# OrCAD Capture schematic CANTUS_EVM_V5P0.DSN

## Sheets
1 01. CANTUS: size A3; title: CANTUS EVM BOARD
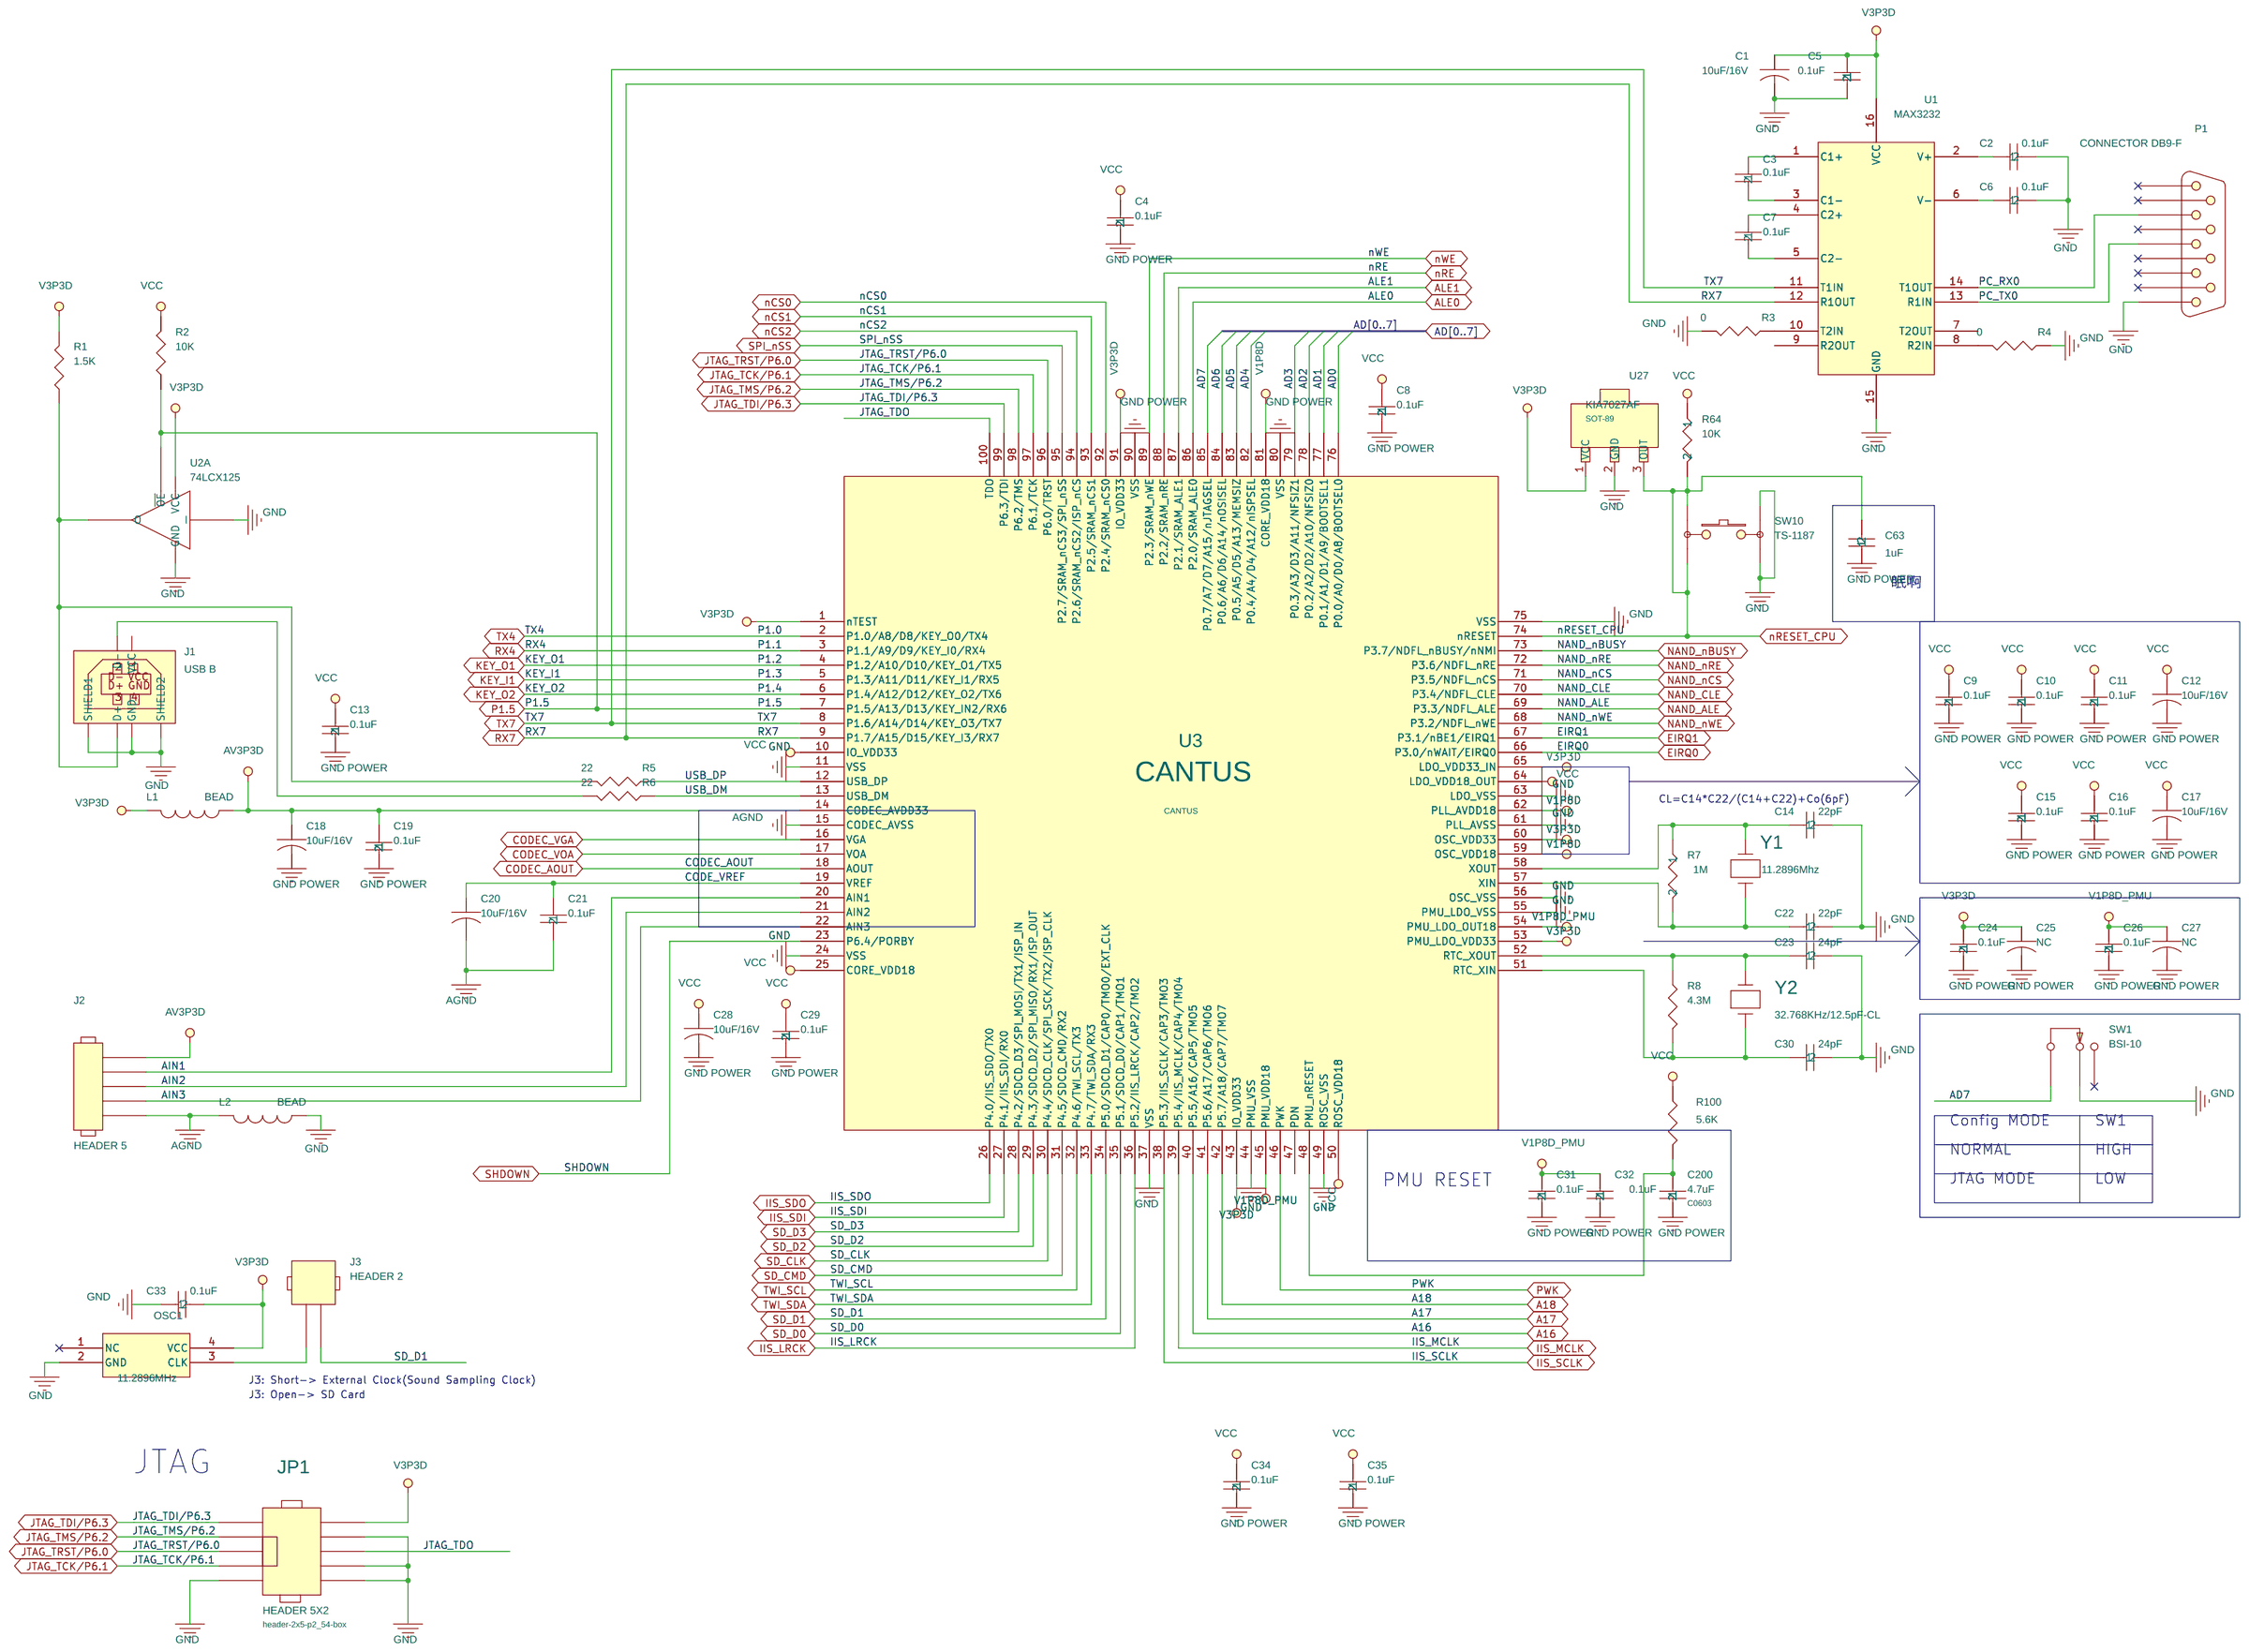
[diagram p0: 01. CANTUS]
2 02. CANTUS Audio DAC & KEY: size A3; rev: 5.0; note: CANTUS DAC & KEY
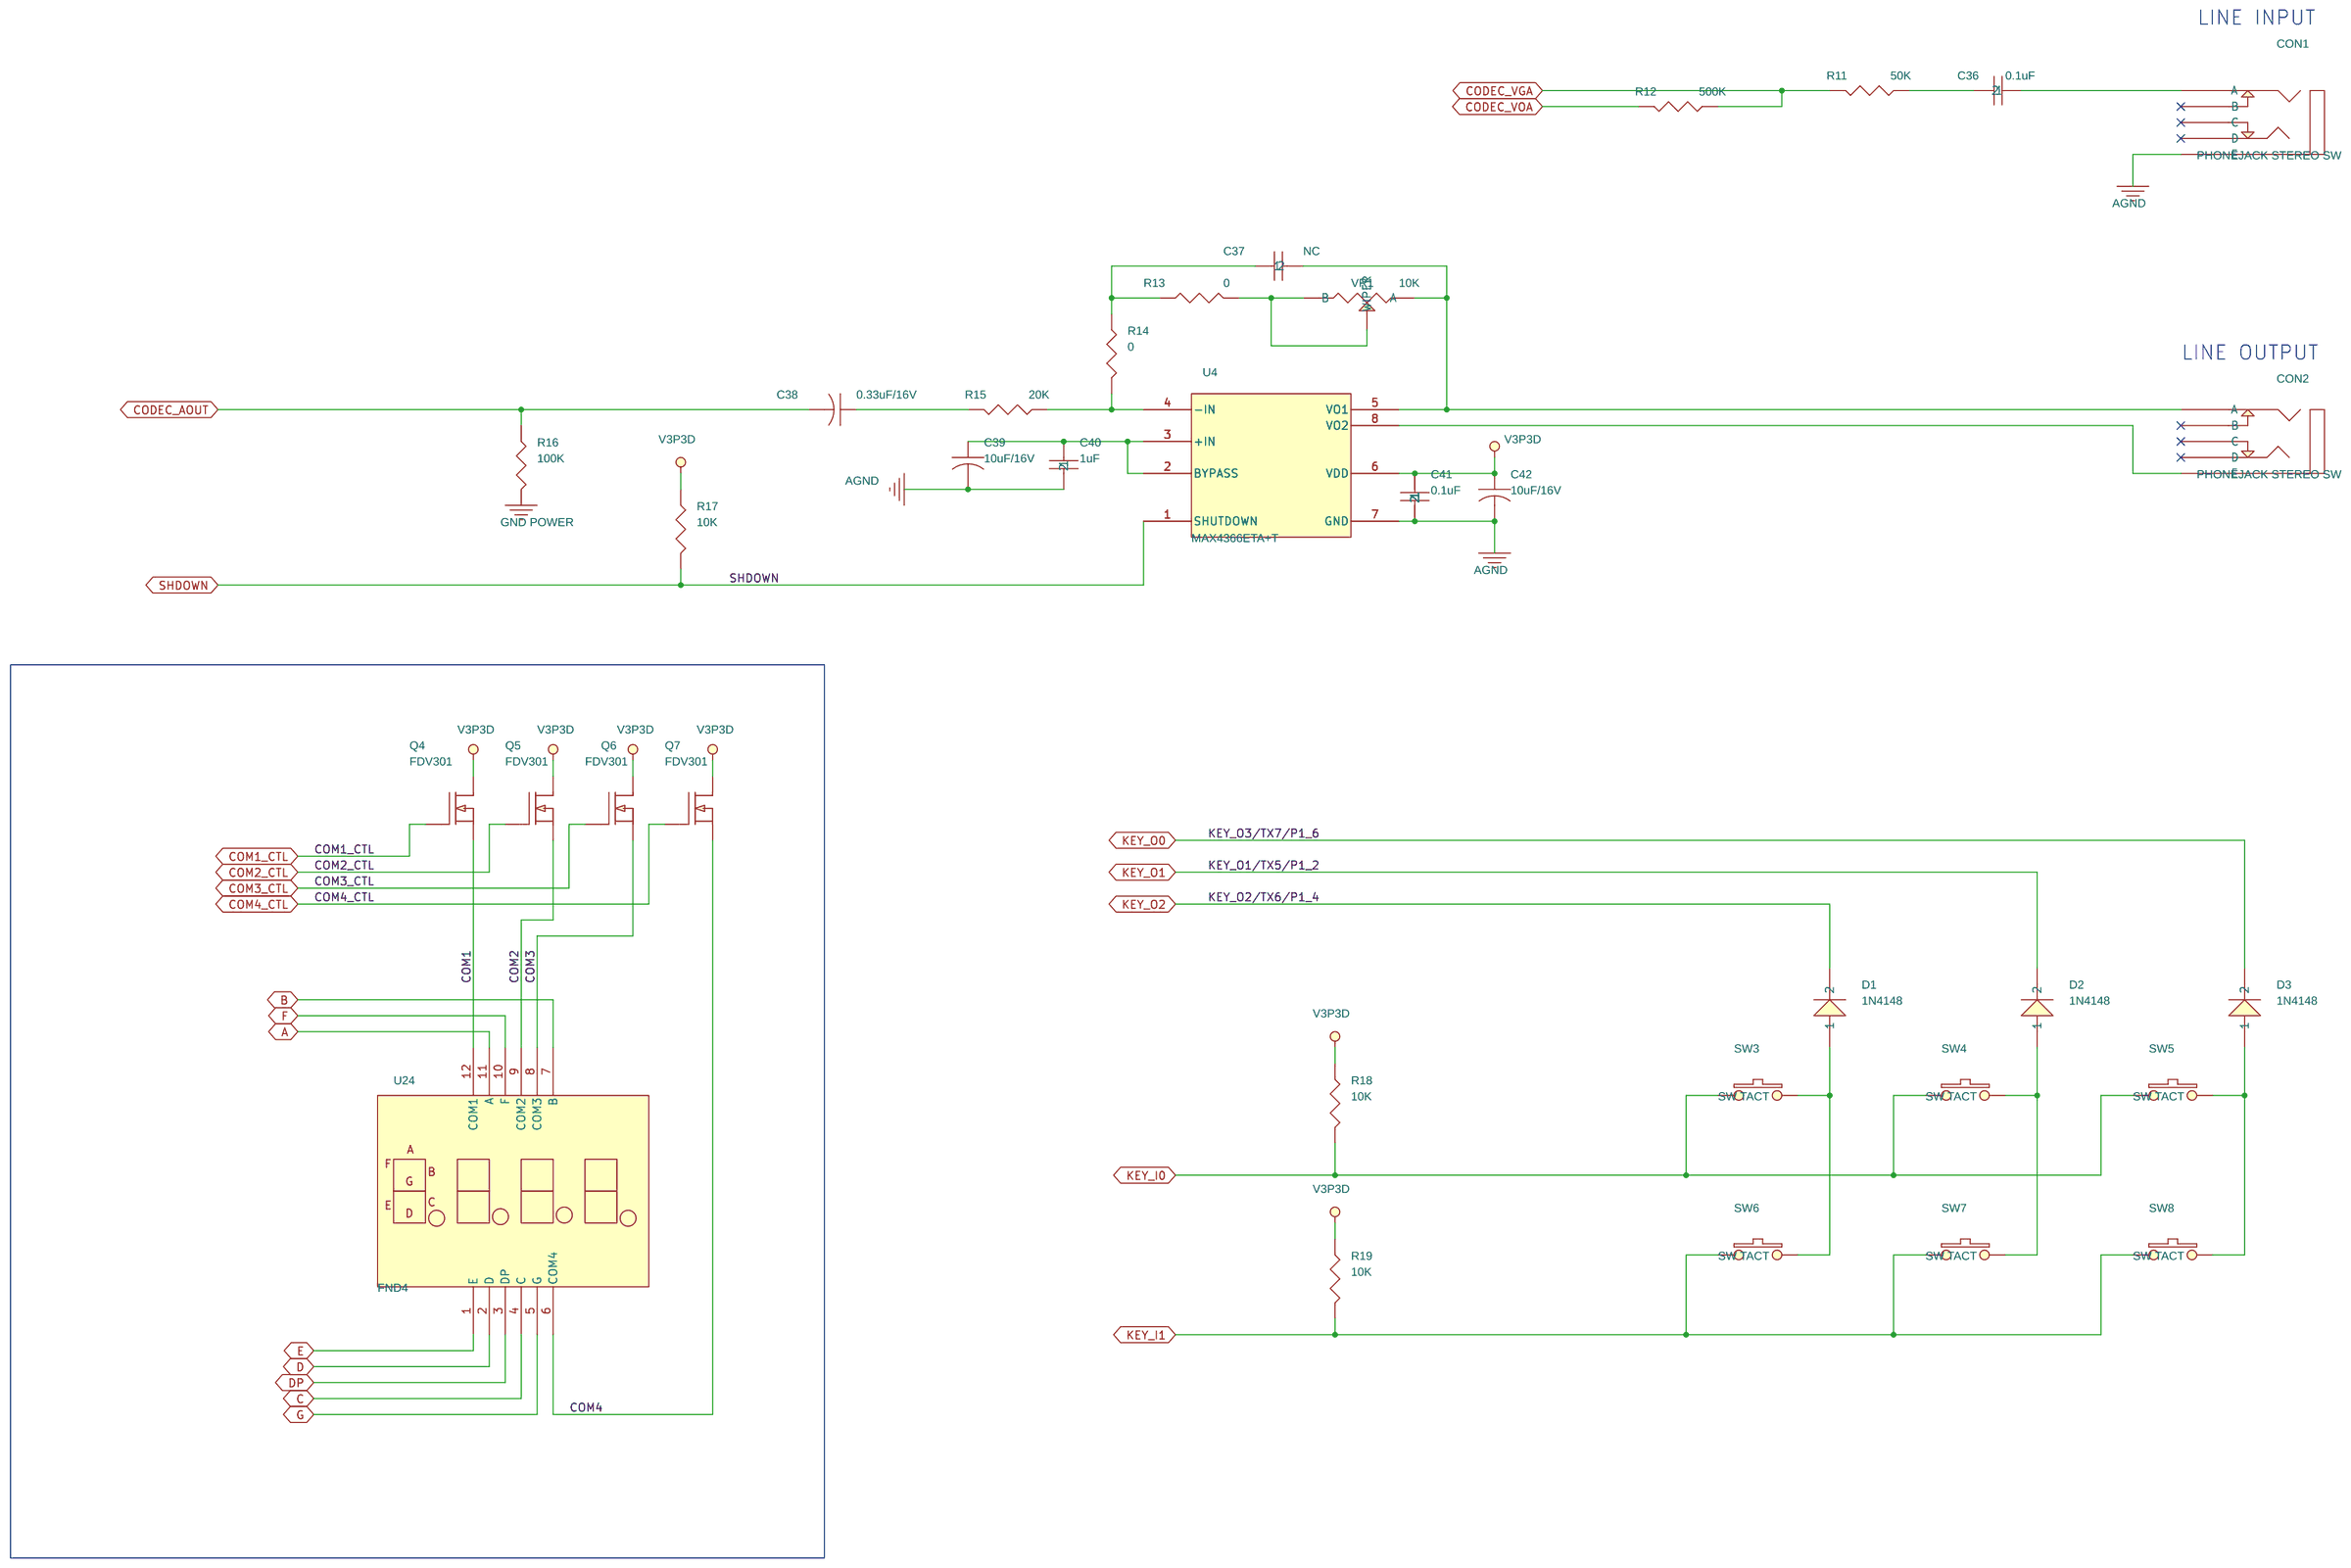
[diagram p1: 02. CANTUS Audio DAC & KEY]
3 03. Buffer: size A3
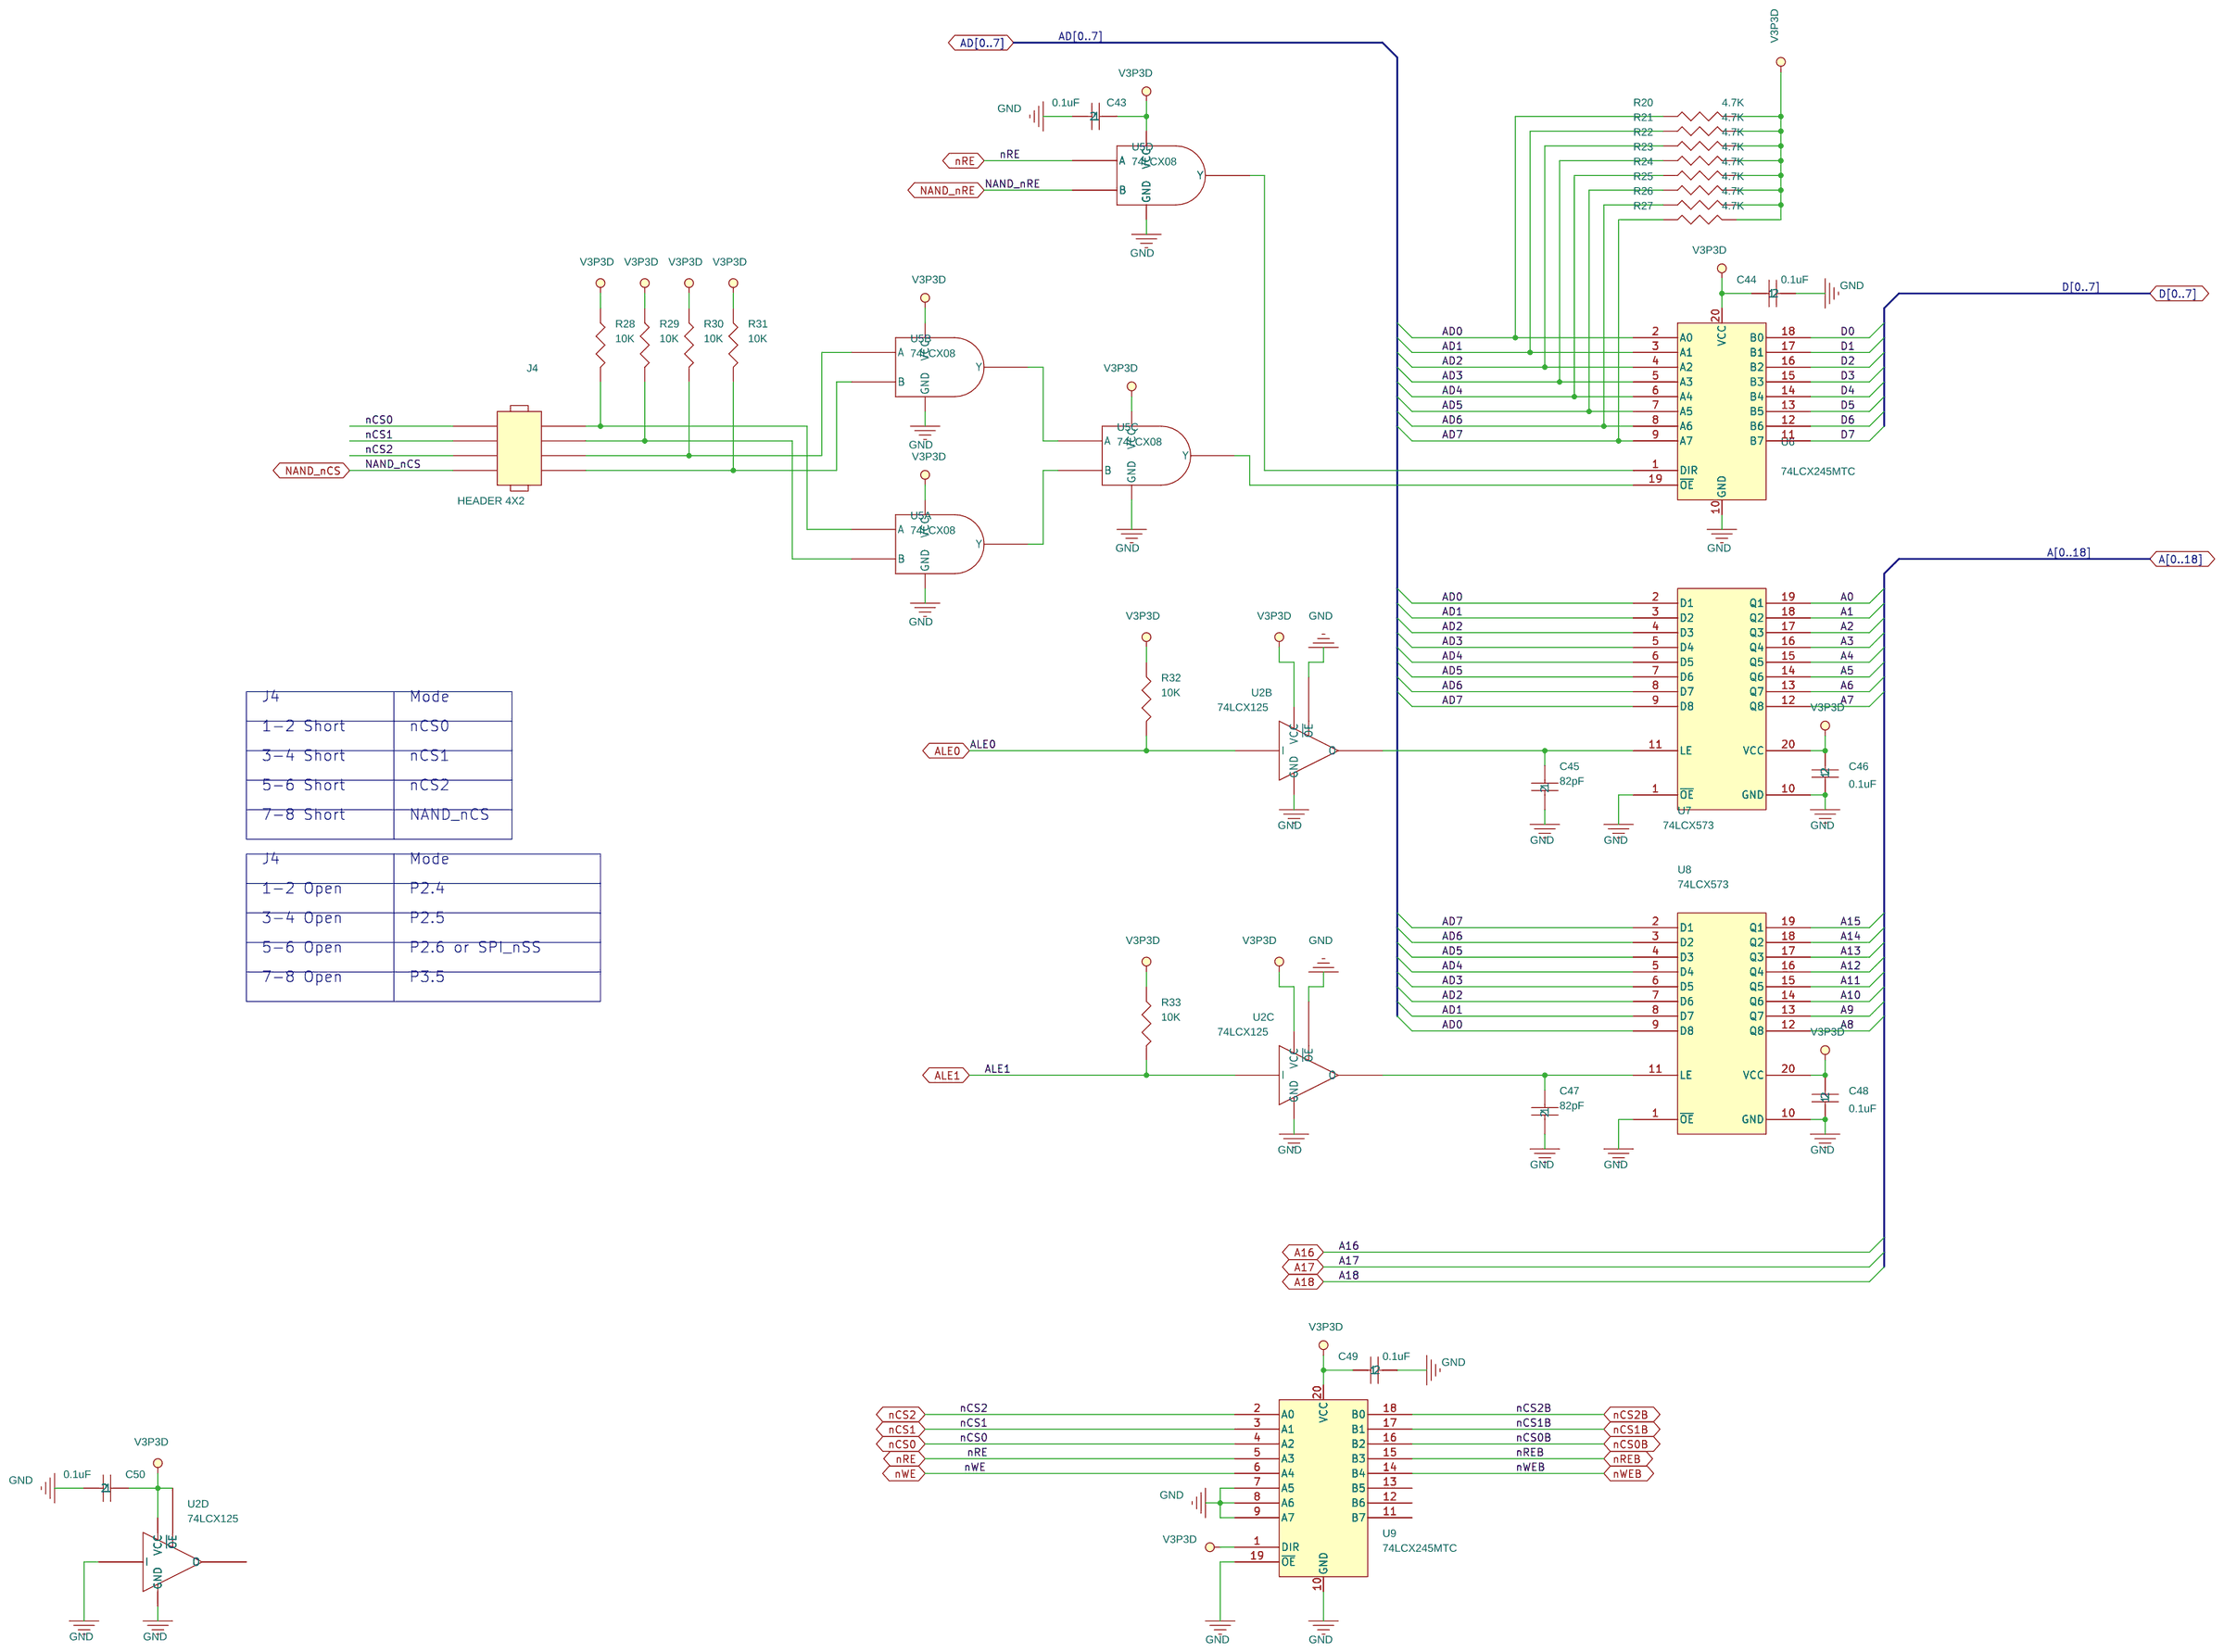
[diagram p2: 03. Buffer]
4 04 Memory: size A3; rev: 5.0; note: SRAM,NAND,EEPROM, SPI FLASH
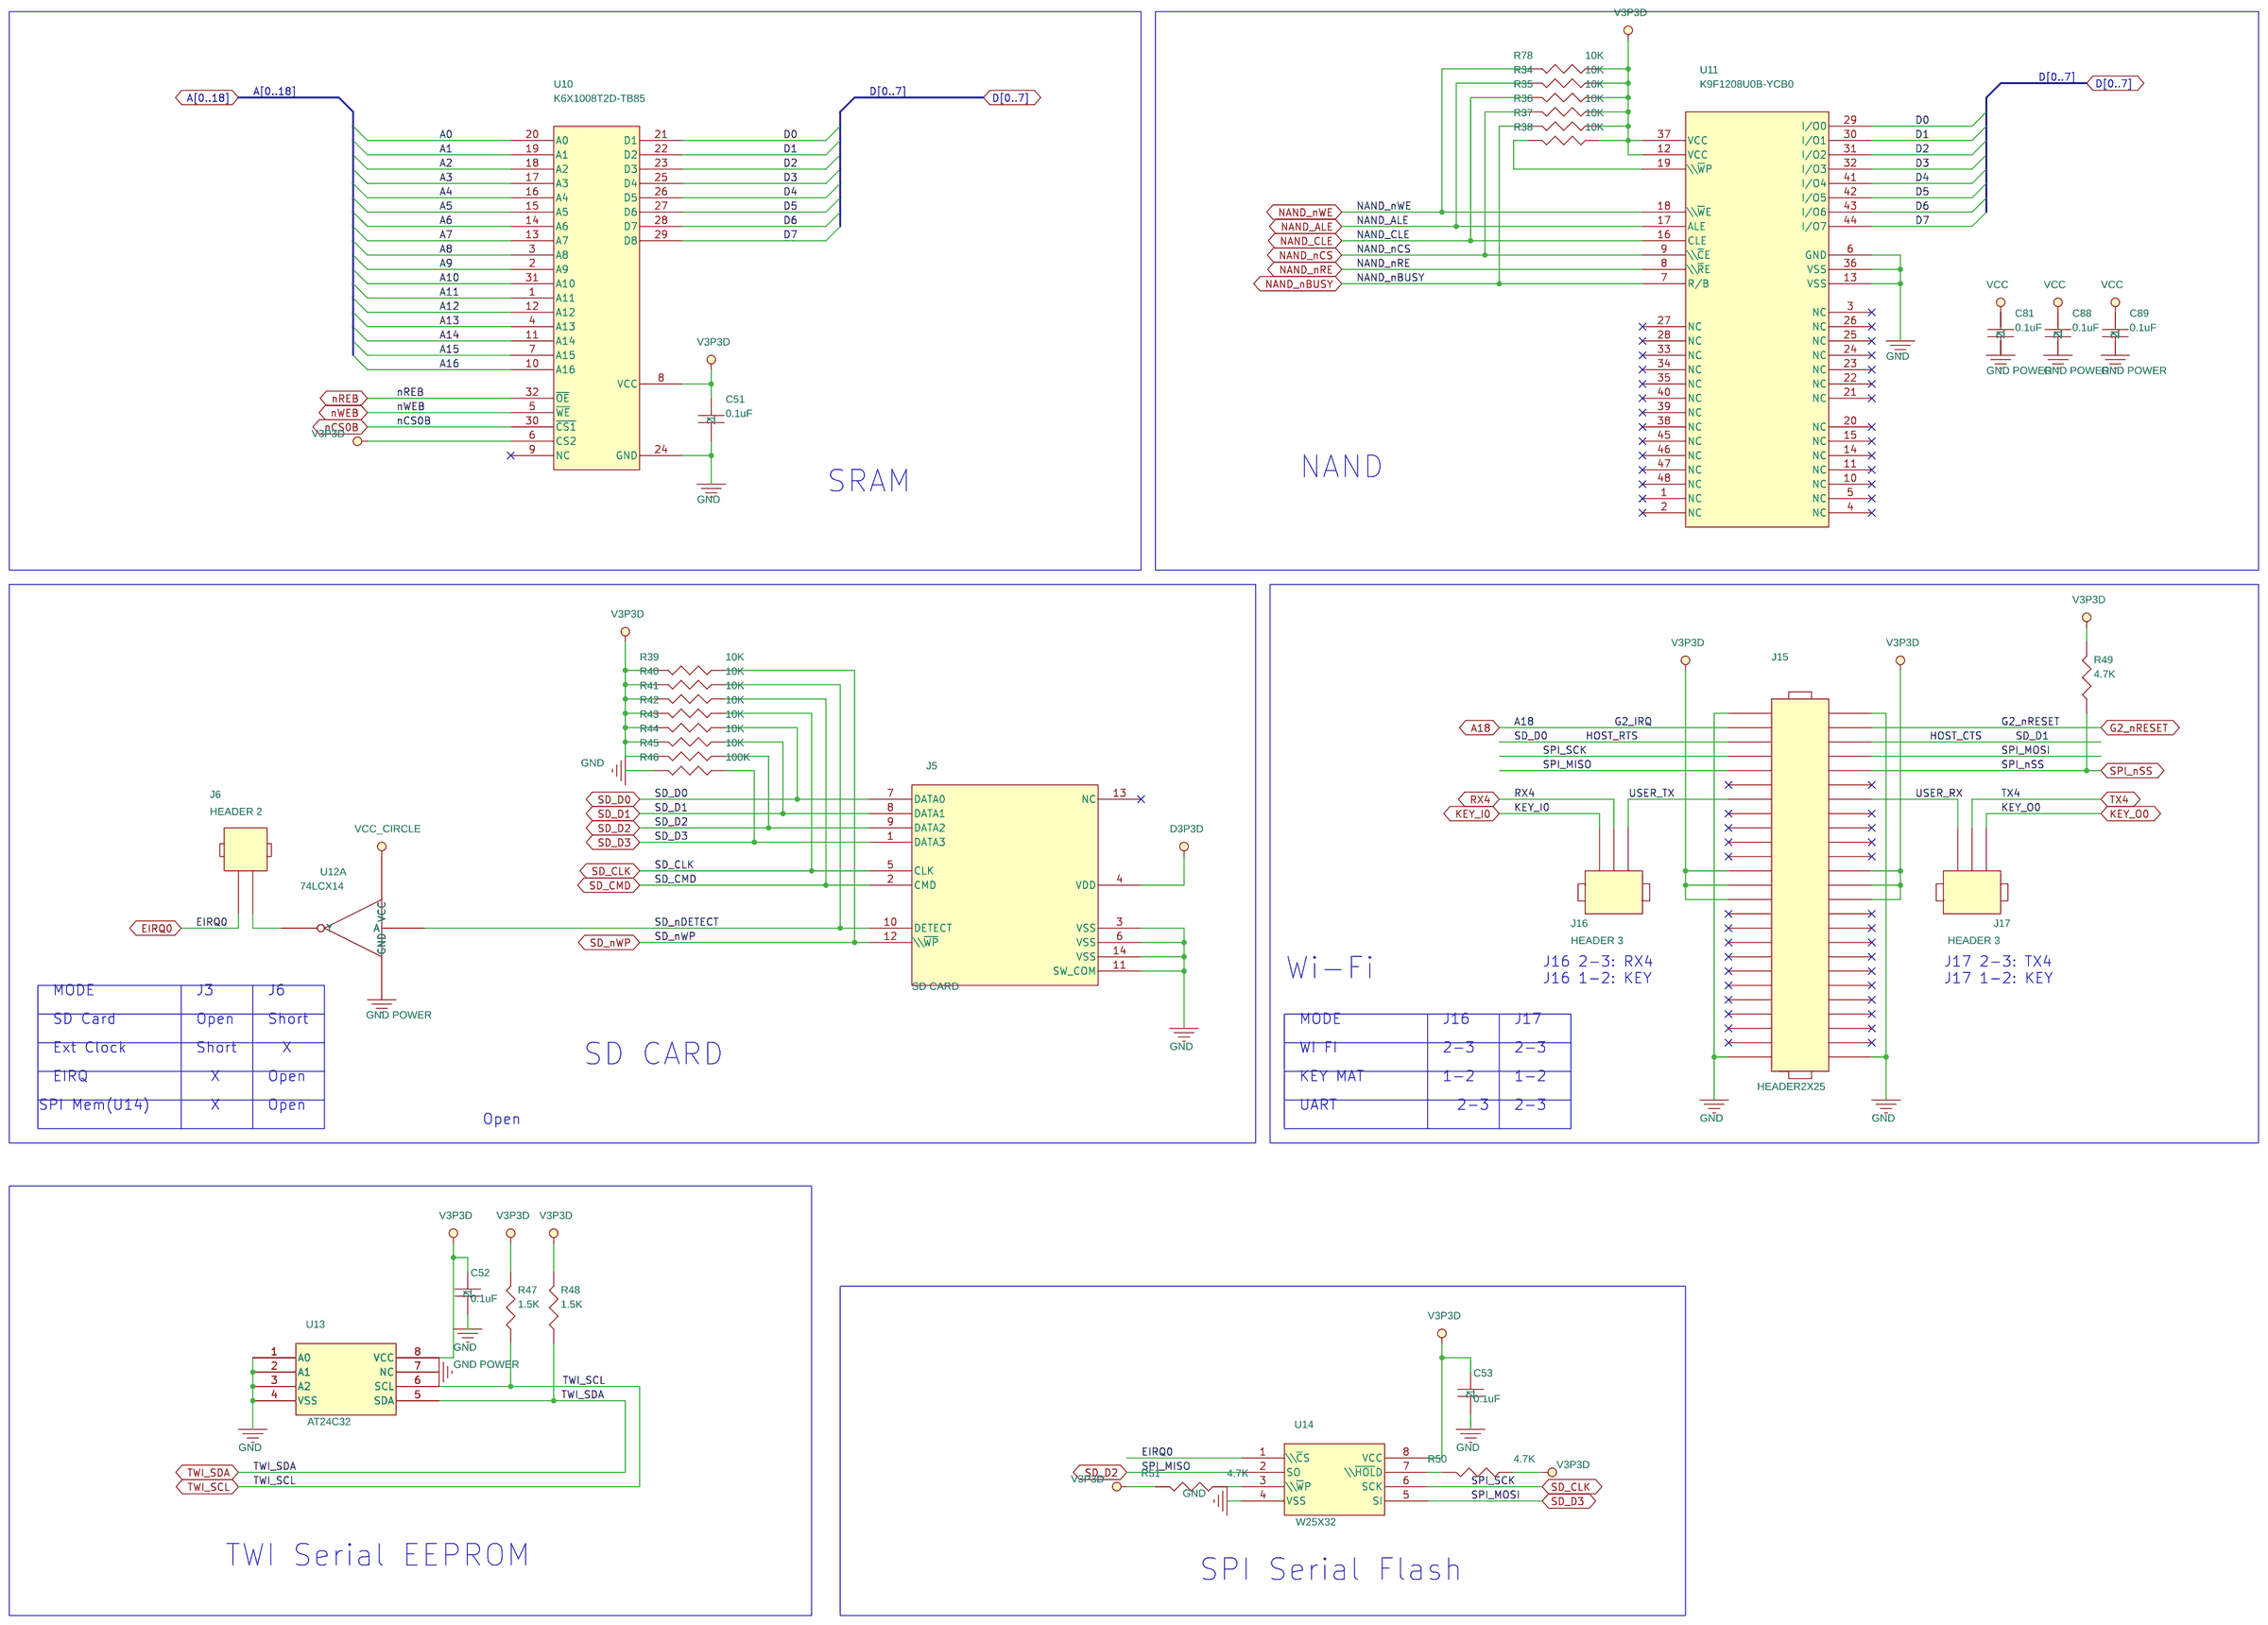
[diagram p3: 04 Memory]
5 05. Decoder: size A3; rev: 5.0; note: Decoder & LED & Control
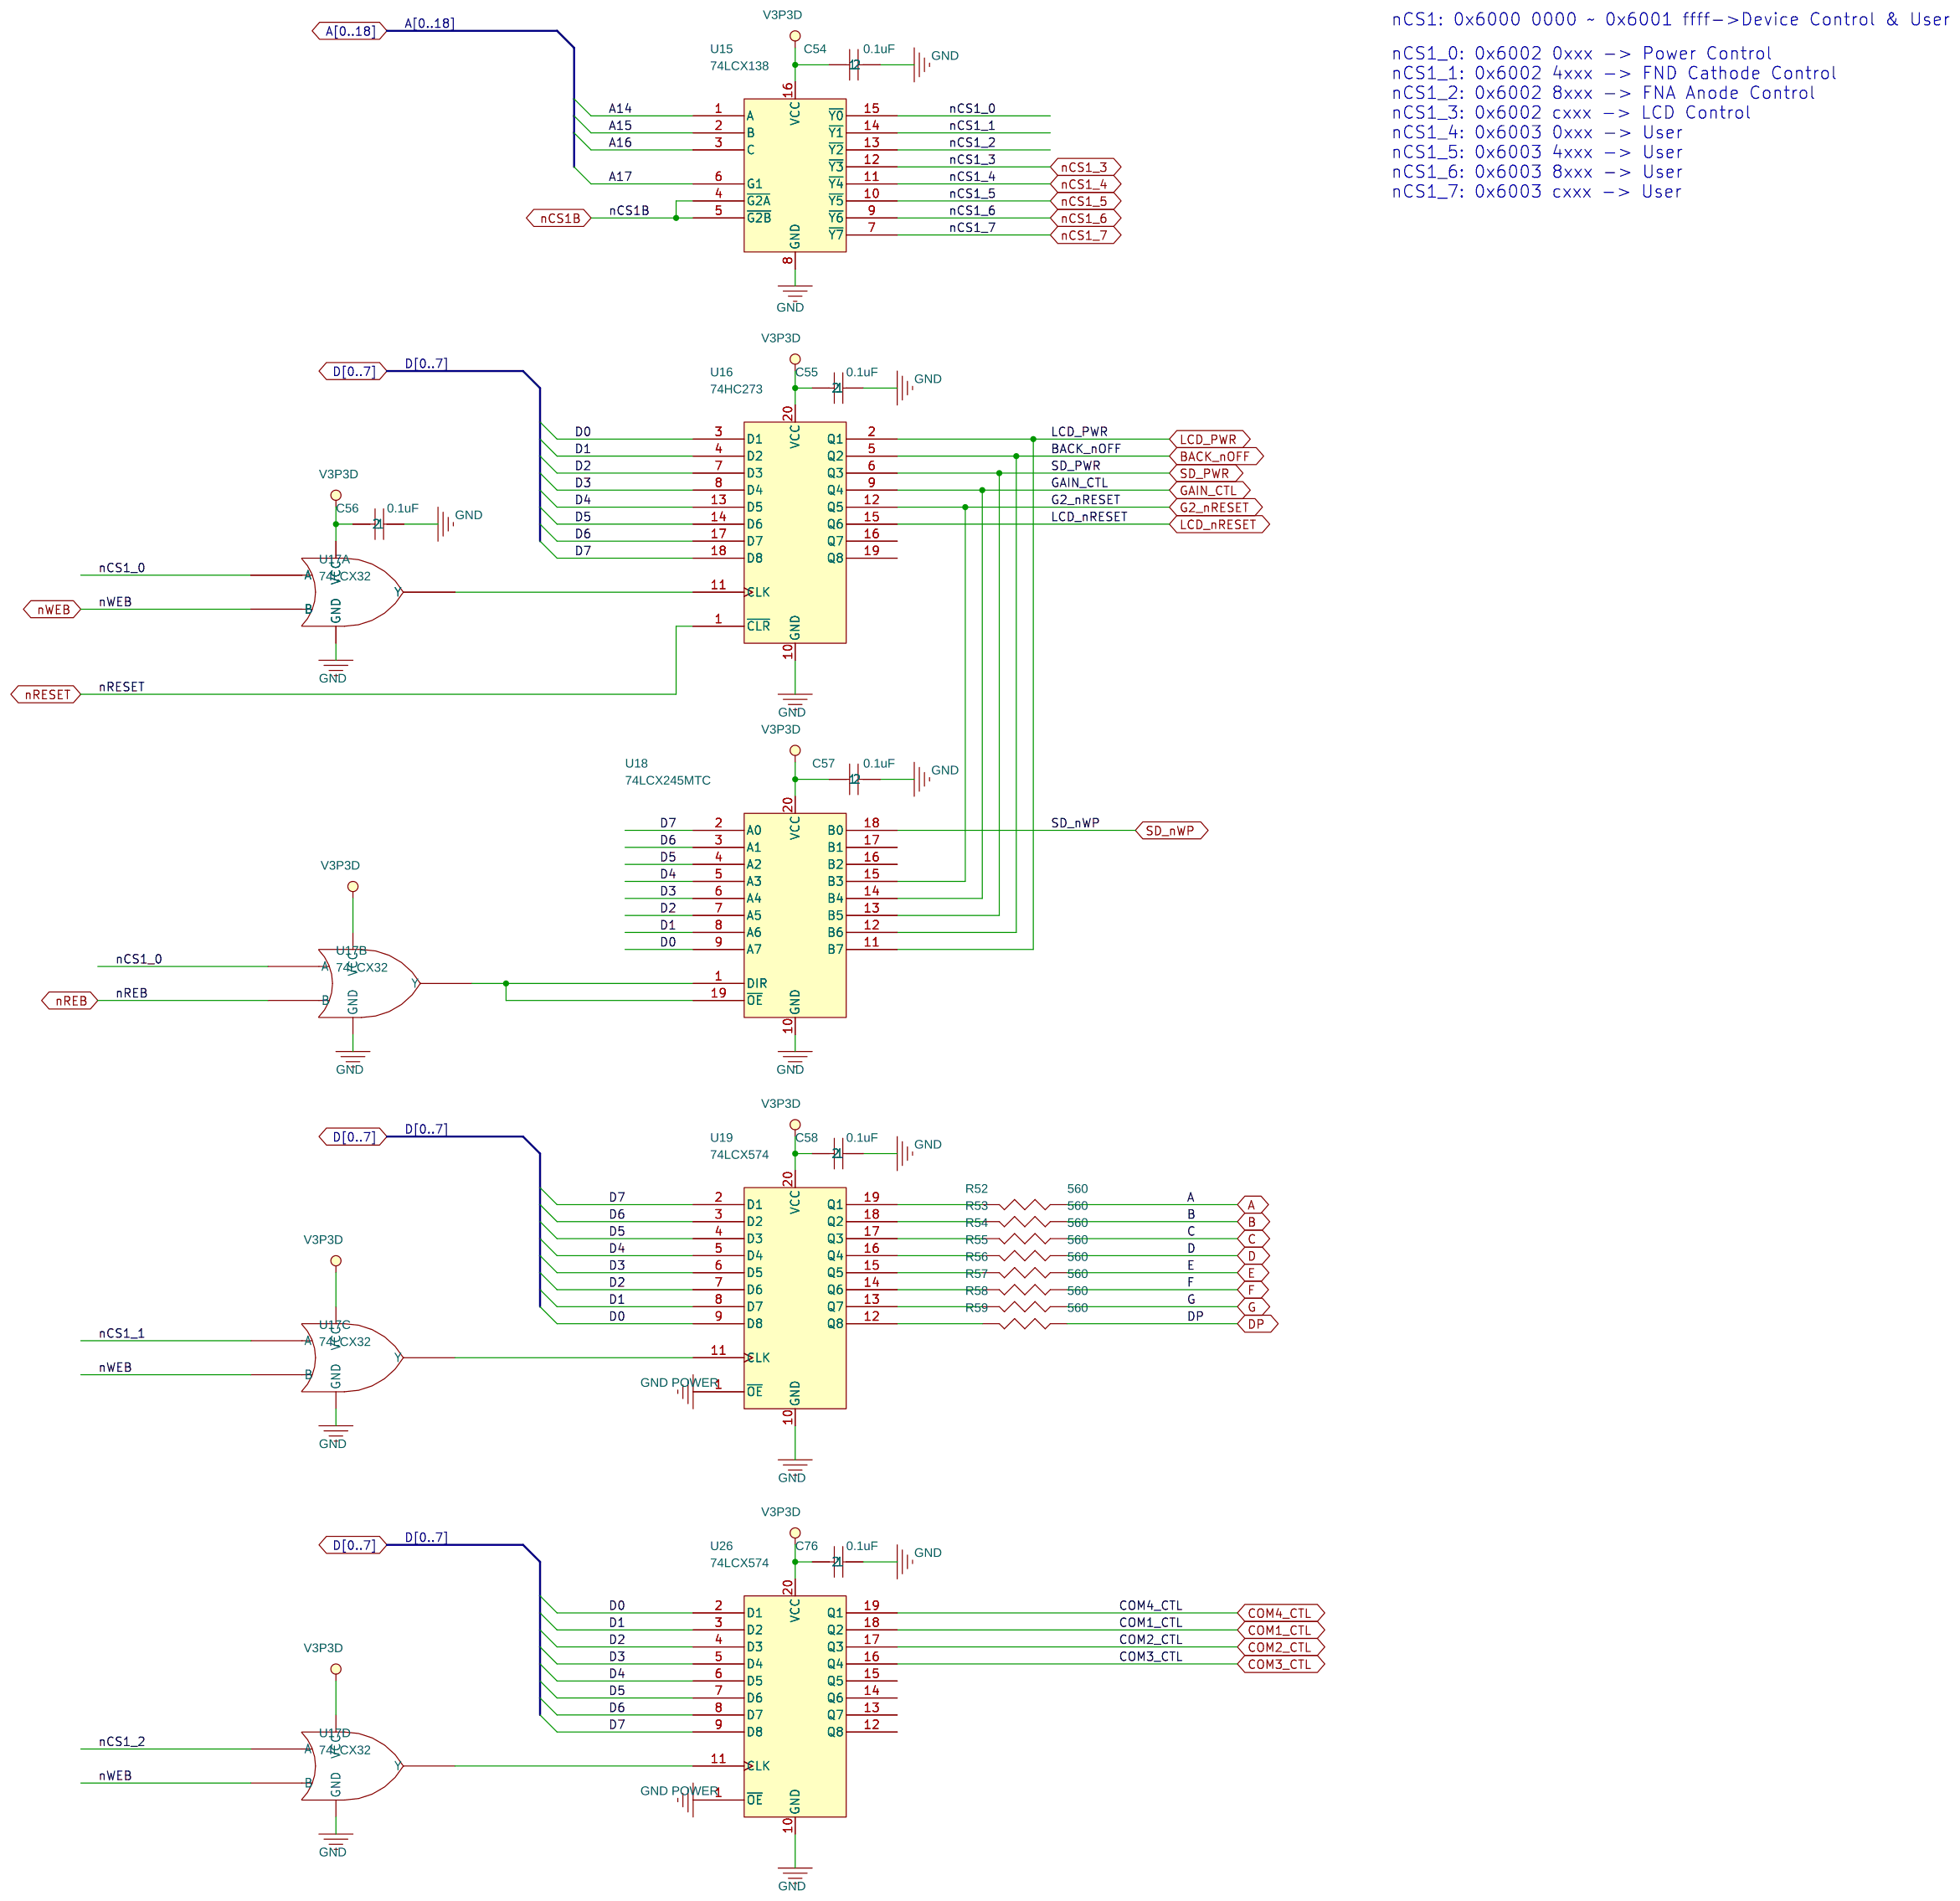
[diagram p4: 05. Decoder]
6 06 LCD: size A3
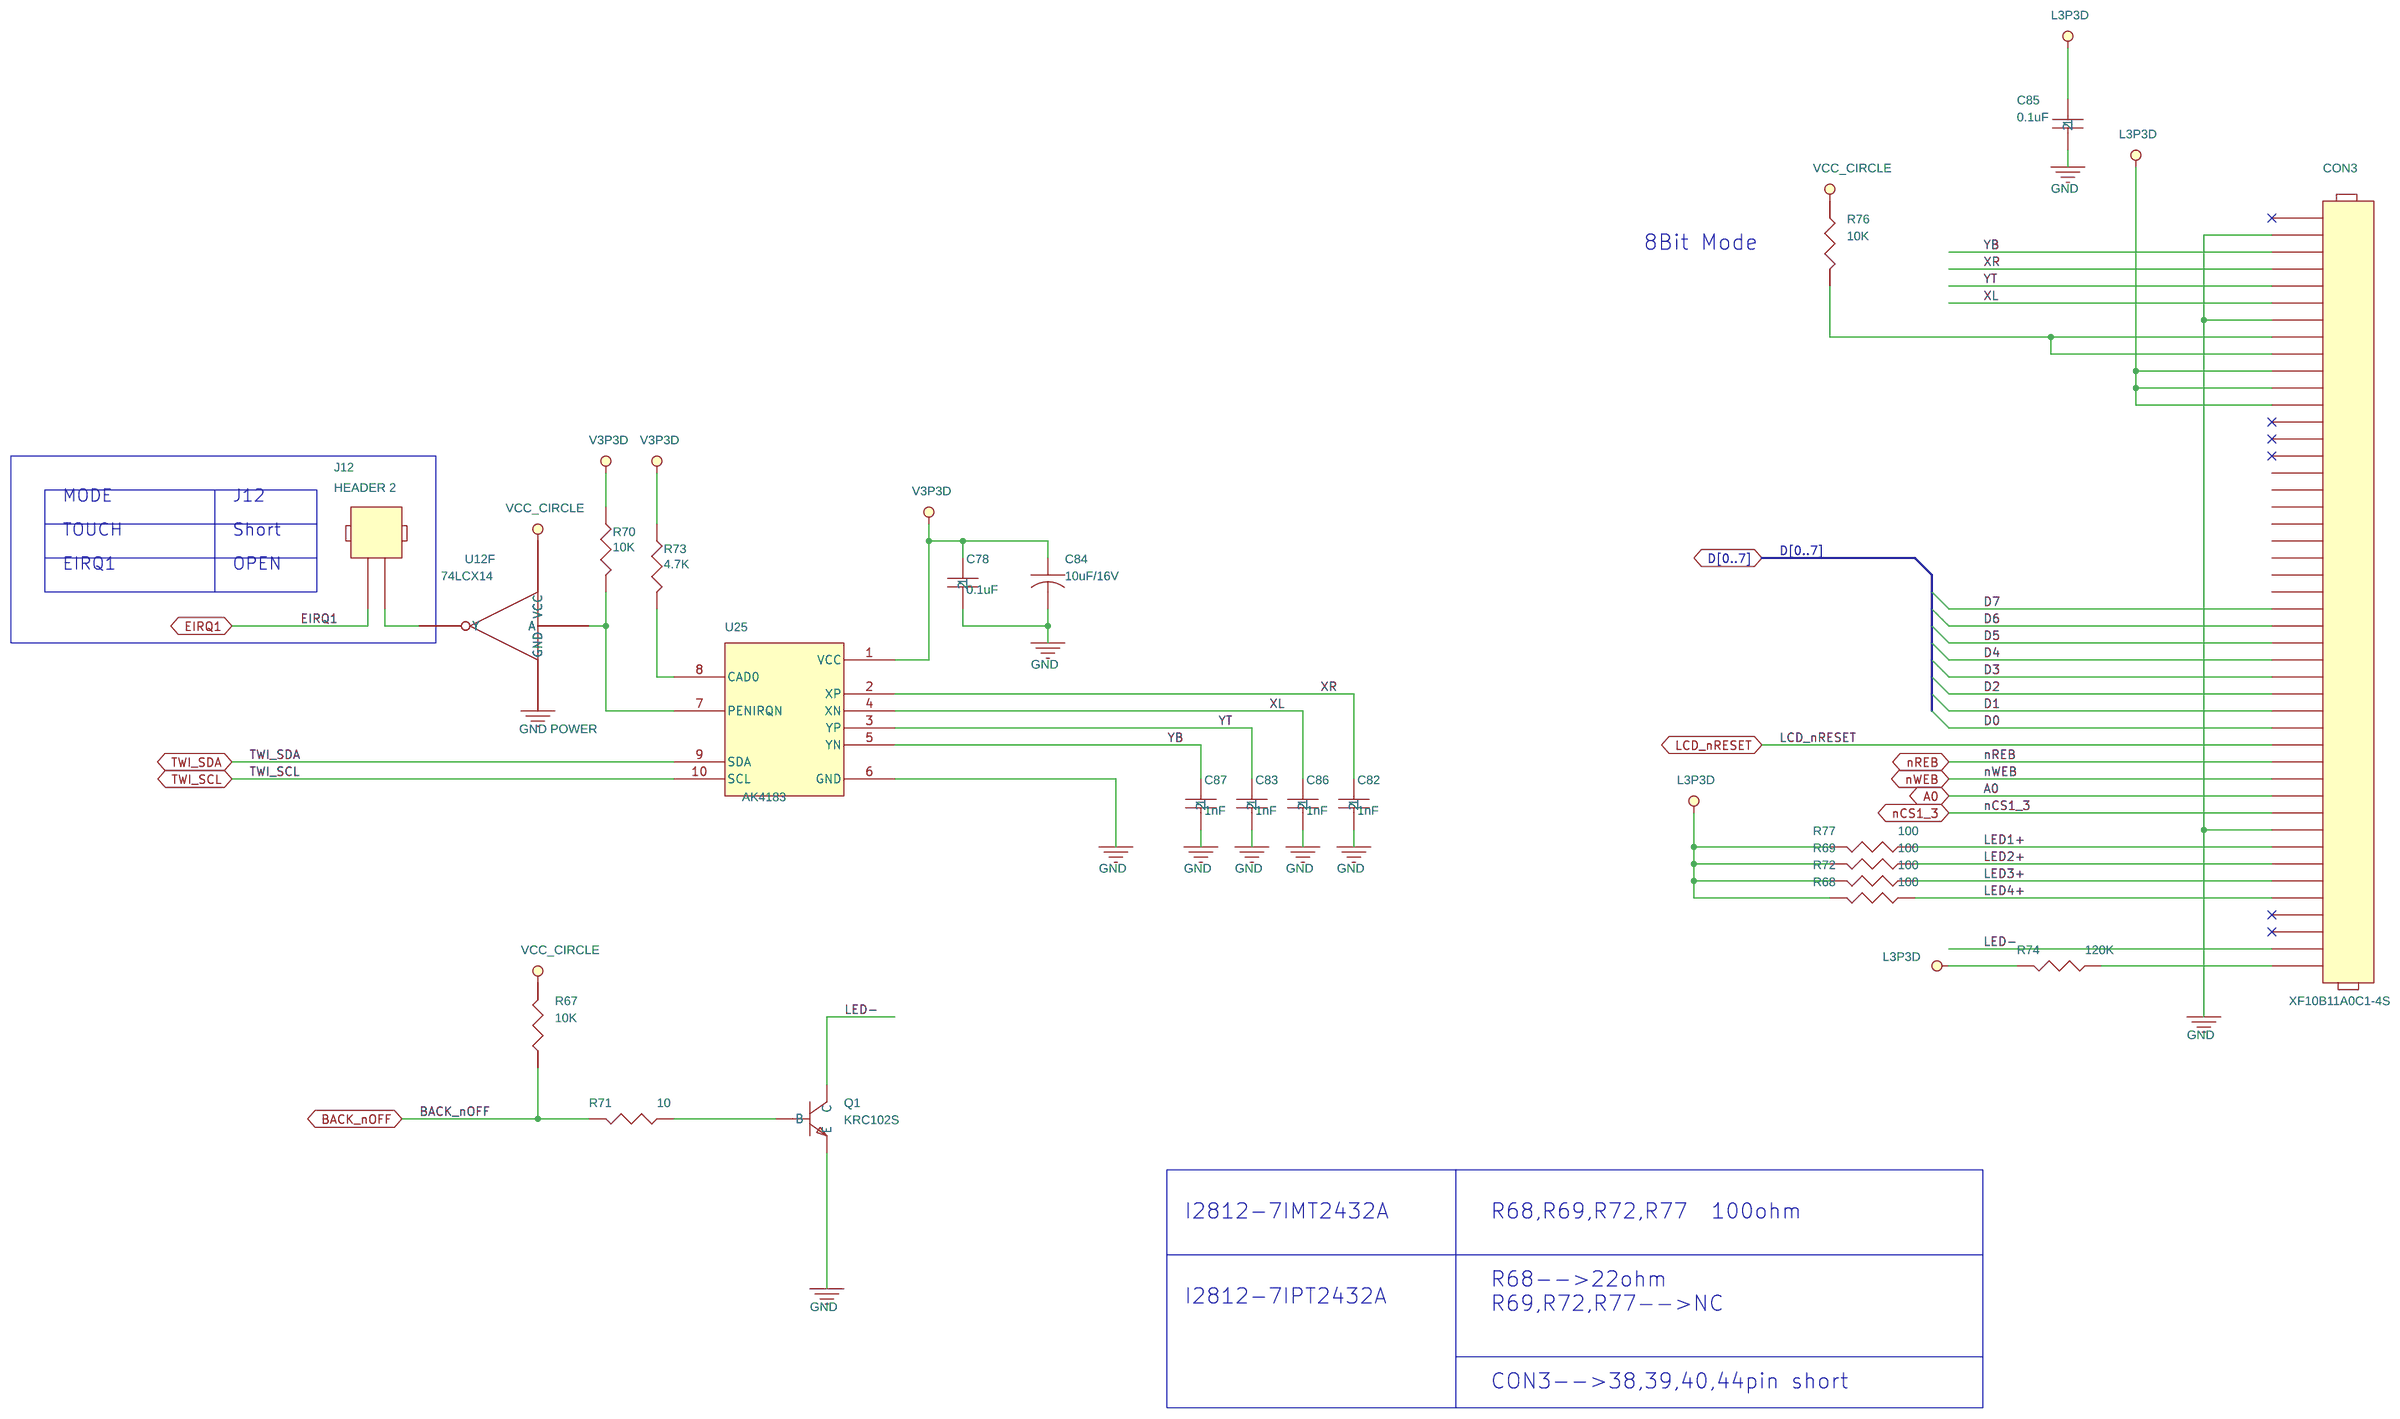
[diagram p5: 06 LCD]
7 07. External Connector: size A3; rev: 5.0; note: External Port
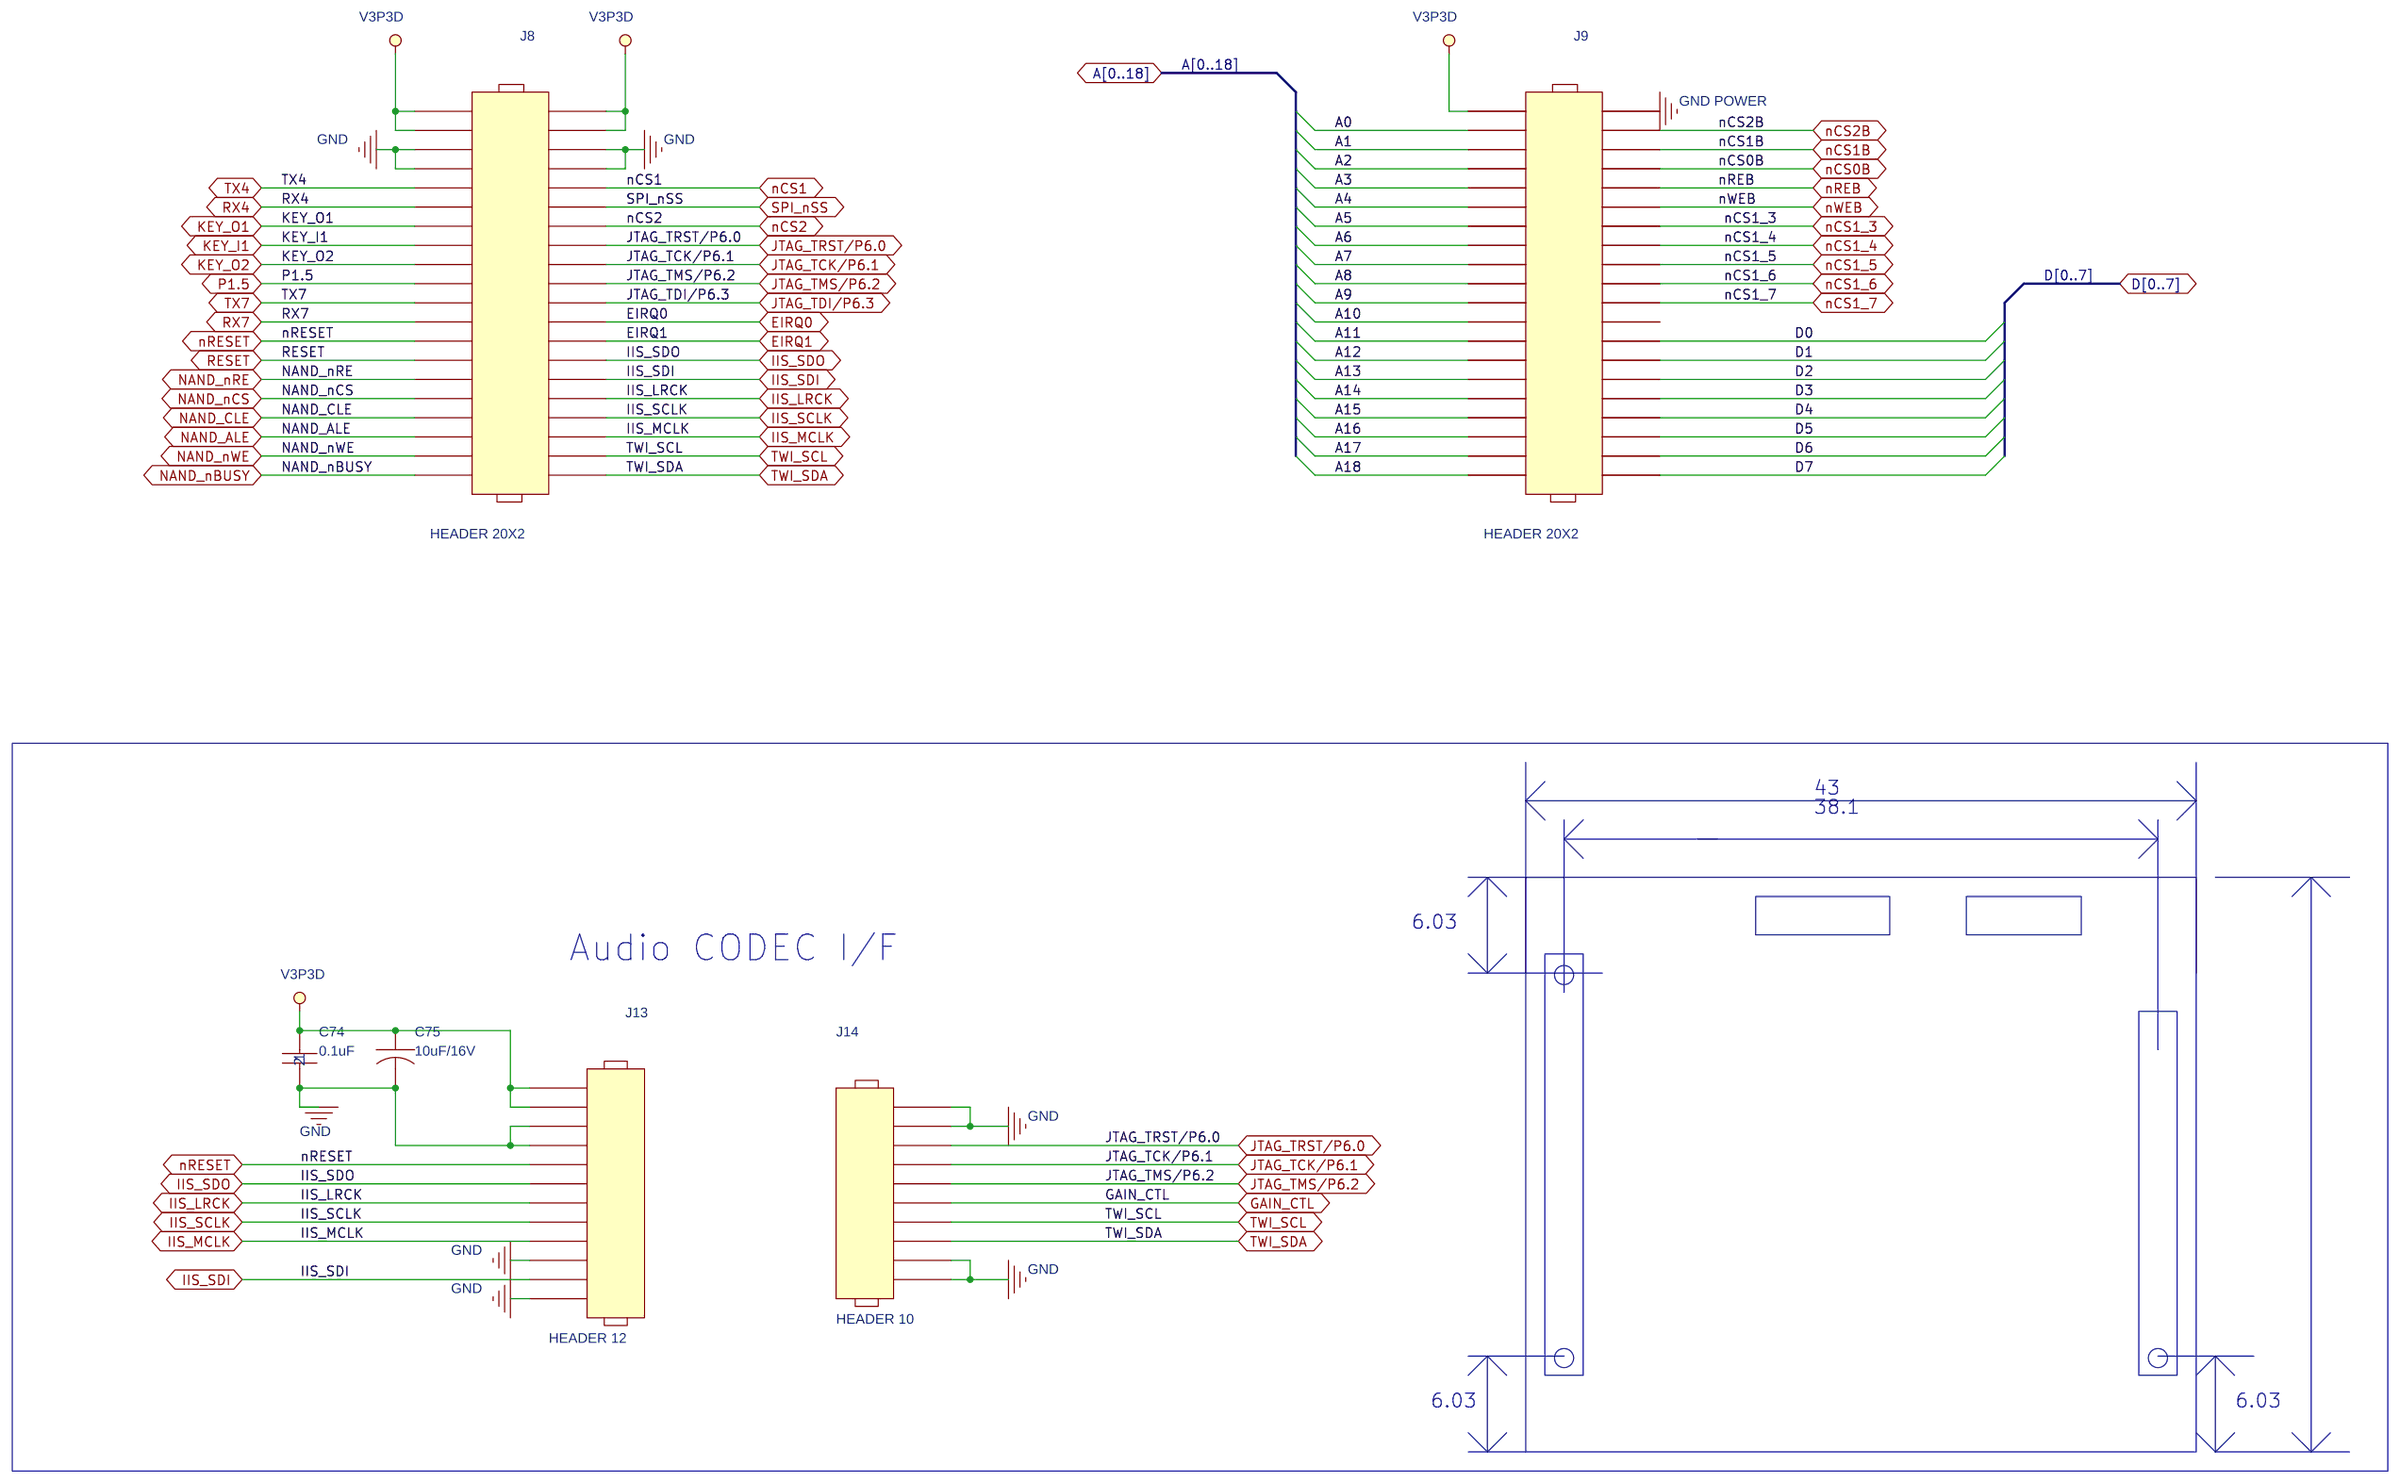
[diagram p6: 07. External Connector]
8 08. Power & Reset: size A3; rev: 5.0; note: POWER & RESET
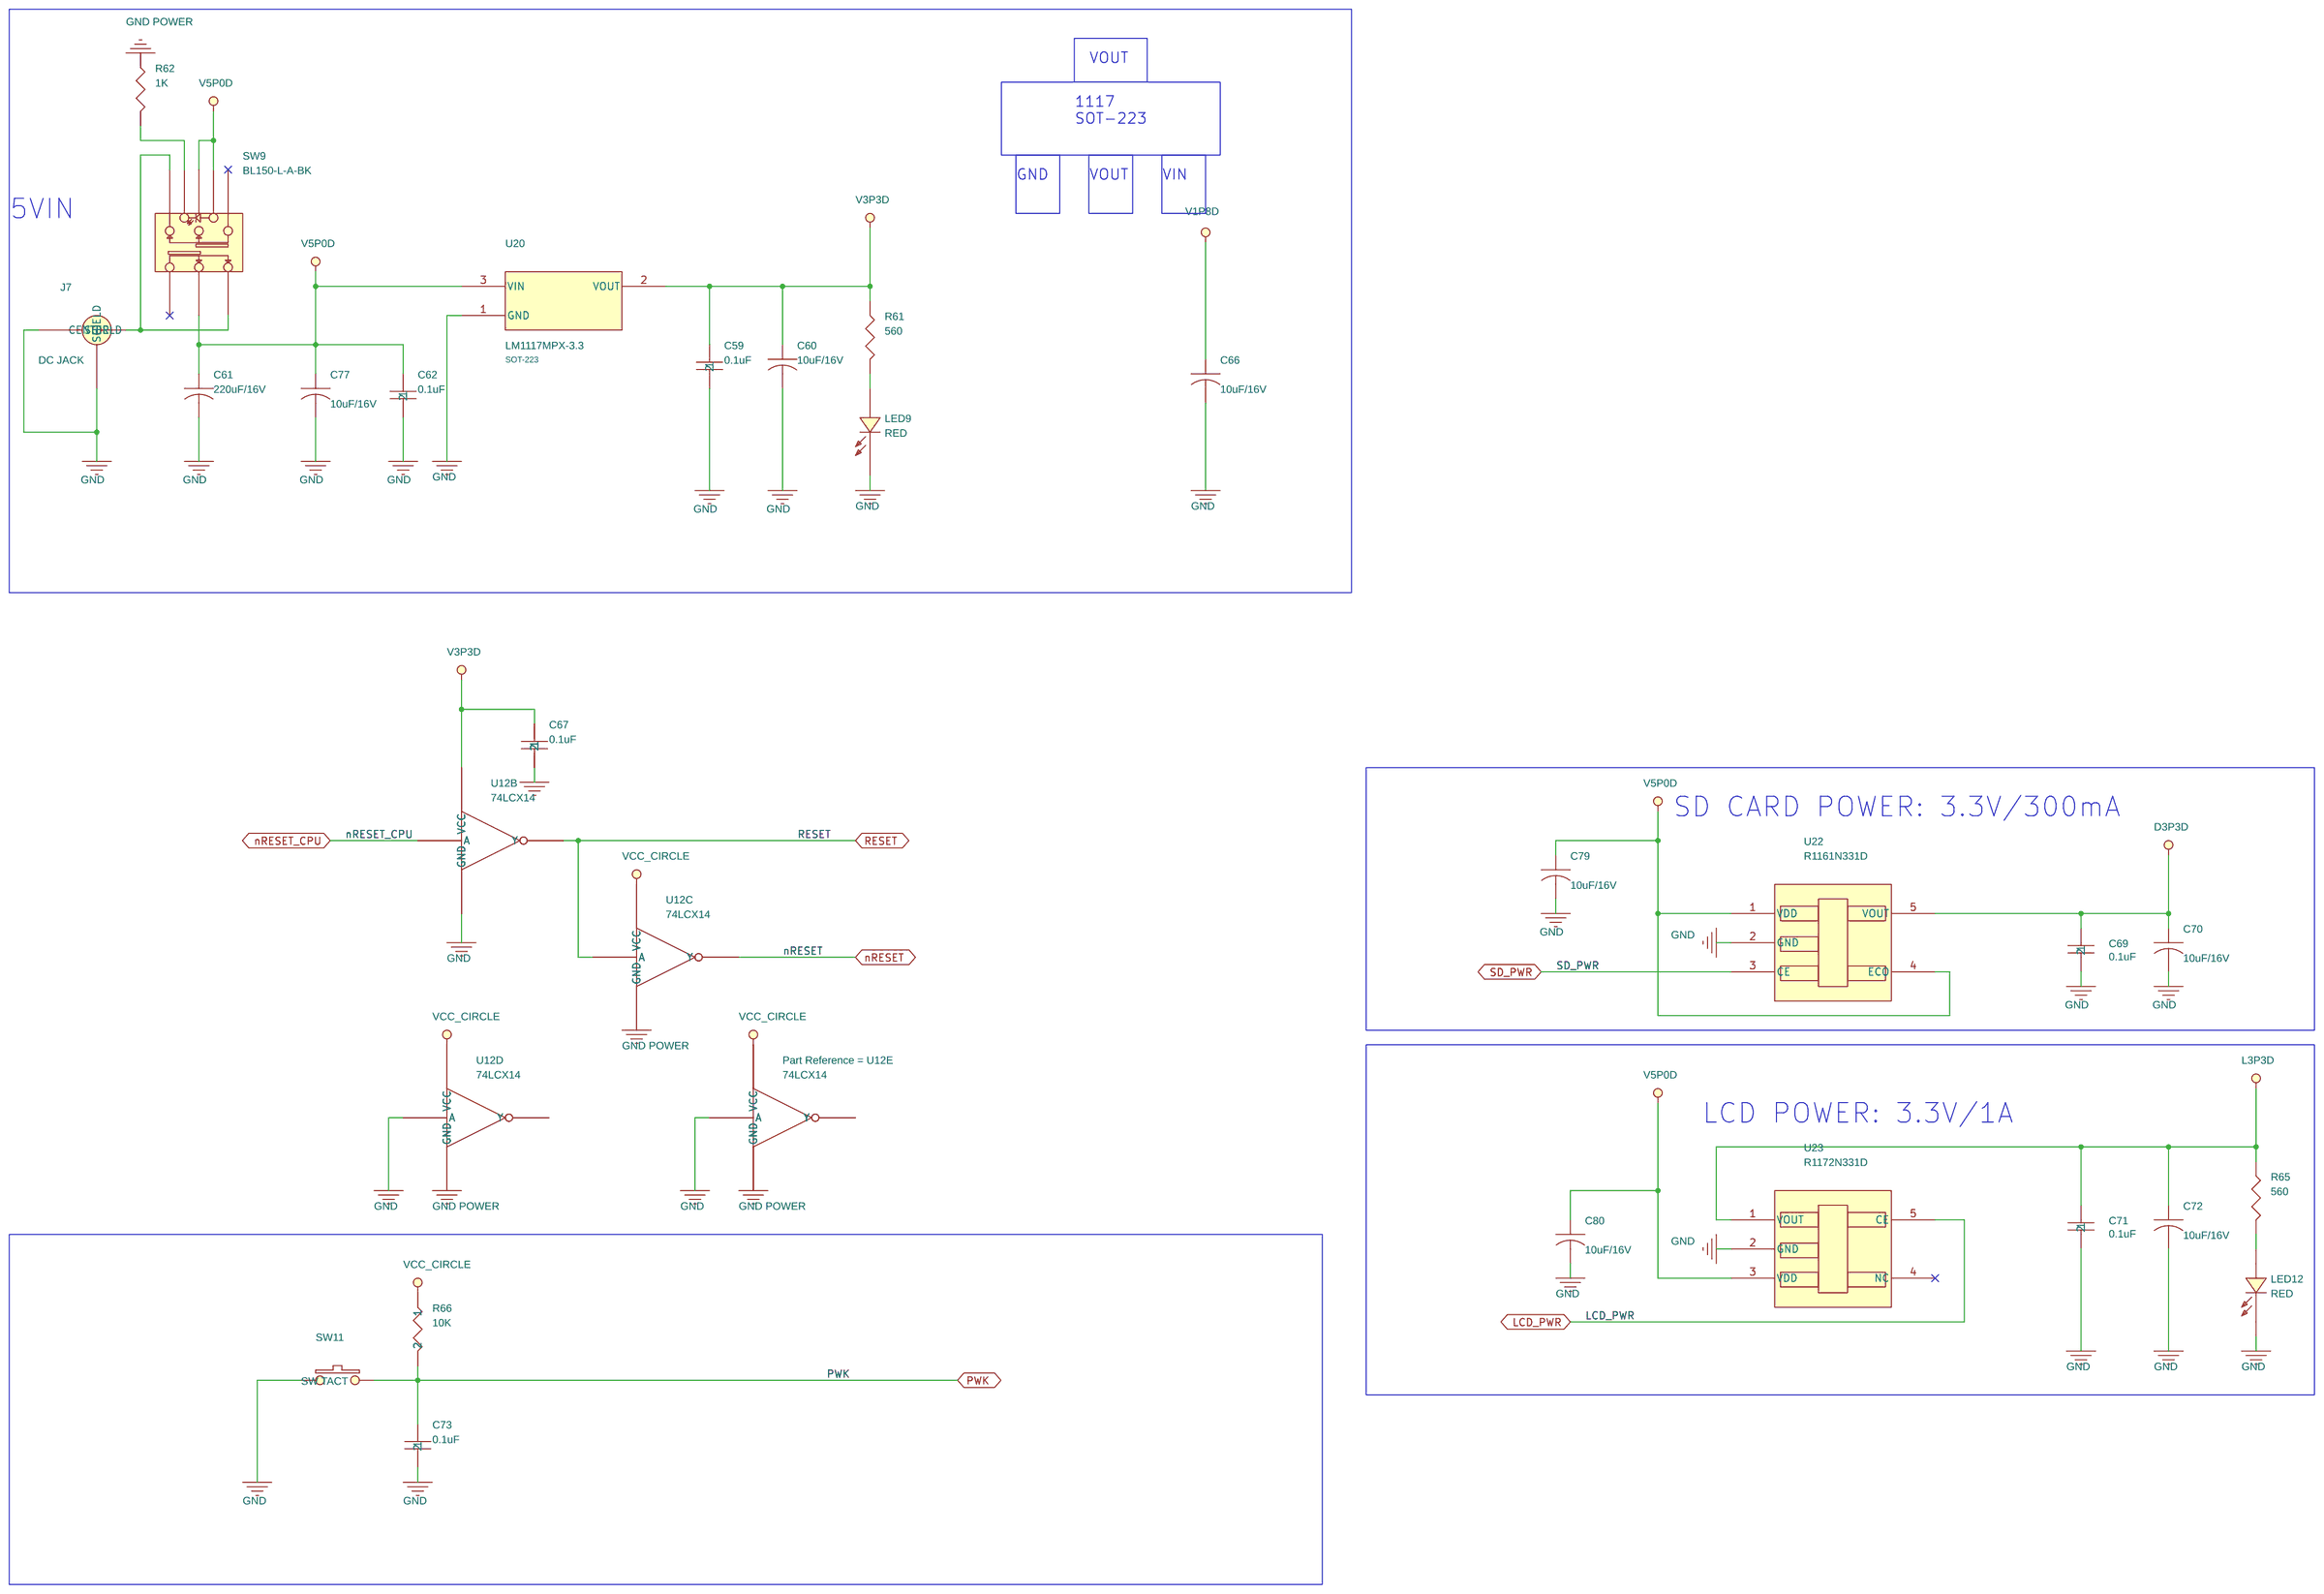
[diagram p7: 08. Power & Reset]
9 09 History
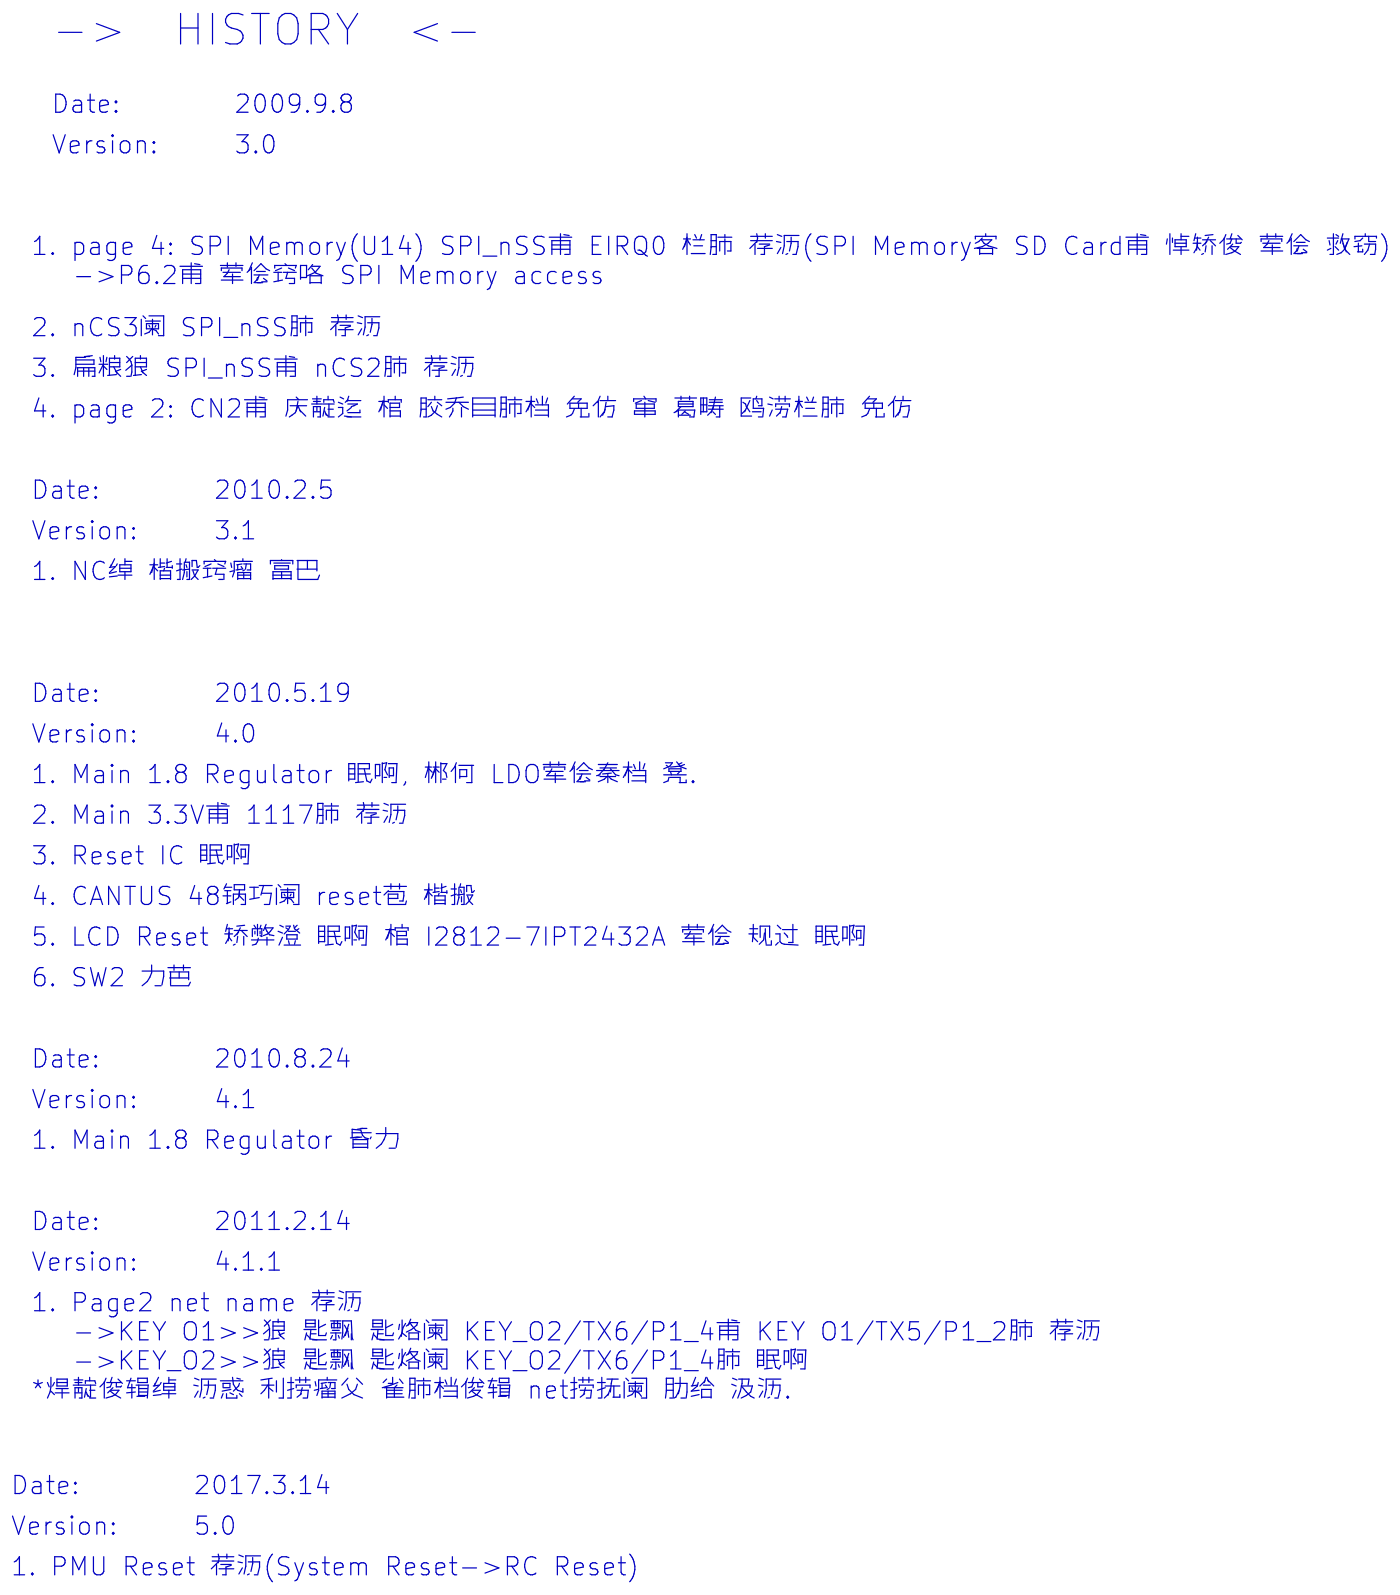
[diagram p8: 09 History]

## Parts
sheet 01. CANTUS
C1  10uF/16V
C2  0.1uF
C3  0.1uF
C4  0.1uF
C5  0.1uF
C6  0.1uF
C7  0.1uF
C8  0.1uF
C9  0.1uF
C10  0.1uF
C11  0.1uF
C12  10uF/16V
C13  0.1uF
C14  22pF
C15  0.1uF
C16  0.1uF
C17  10uF/16V
C18  10uF/16V
C19  0.1uF
C20  10uF/16V
C21  0.1uF
C22  22pF
C23  24pF
C24  0.1uF
C25  NC
C26  0.1uF
C27  NC
C28  10uF/16V
C29  0.1uF
C30  24pF
C31  0.1uF
C32  0.1uF
C33  0.1uF
C34  0.1uF
C35  0.1uF
C63  1uF
C200  4.7uF  [C0603]
J1  USB B
J2  HEADER 5
J3  HEADER 2
JP1  HEADER 5X2  [header-2x5-p2_54-box]
L1  BEAD
L2  BEAD
OSC1  11.2896MHz
P1  CONNECTOR DB9-F
R1  1.5K
R2  10K
R3  0
R4  0
R5  22
R6  22
R7  1M
R8  4.3M
R64  10K
R100  5.6K
SW1  BSI-10
SW10  TS-1187
U1  MAX3232
U2  74LCX125  (sections A,B,C,D)
U3  CANTUS  [CANTUS]
U27  KIA7027AF  [SOT-89]
Y1  11.2896Mhz
Y2  32.768KHz/12.5pF-CL
sheet 02. CANTUS Audio DAC & KEY
C36  0.1uF
C37  NC
C38  0.33uF/16V
C39  10uF/16V
C40  1uF
C41  0.1uF
C42  10uF/16V
CON1  PHONEJACK STEREO SW
CON2  PHONEJACK STEREO SW
D1  1N4148
D2  1N4148
D3  1N4148
Q4  FDV301
Q5  FDV301
Q6  FDV301
Q7  FDV301
R11  50K
R12  500K
R13  0
R14  0
R15  20K
R16  100K
R17  10K
R18  10K
R19  10K
SW3  SW TACT
SW4  SW TACT
SW5  SW TACT
SW6  SW TACT
SW7  SW TACT
SW8  SW TACT
U4  MAX4366ETA+T
U24  FND4
VR1  10K
sheet 03. Buffer
C43  0.1uF
C44  0.1uF
C45  82pF
C46  0.1uF
C47  82pF
C48  0.1uF
C49  0.1uF
C50  0.1uF
J4  HEADER 4X2
R20  4.7K
R21  4.7K
R22  4.7K
R23  4.7K
R24  4.7K
R25  4.7K
R26  4.7K
R27  4.7K
R28  10K
R29  10K
R30  10K
R31  10K
R32  10K
R33  10K
U5  74LCX08  (sections A,B,C,D)
U6  74LCX245MTC
U7  74LCX573
U8  74LCX573
U9  74LCX245MTC
sheet 04 Memory
C51  0.1uF
C52  0.1uF
C53  0.1uF
C81  0.1uF
C88  0.1uF
C89  0.1uF
J5  SD CARD  [104G-TAA0-R]
J6  HEADER 2
J15  HEADER2X25
J16  HEADER 3
J17  HEADER 3
R34  10K
R35  10K
R36  10K
R37  10K
R38  10K
R39  10K
R40  10K
R41  10K
R42  10K
R43  10K
R44  10K
R45  10K
R46  100K
R47  1.5K
R48  1.5K
R49  4.7K
R50  4.7K
R51  4.7K
R78  10K
U10  K6X1008T2D-TB85
U11  K9F1208U0B-YCB0
U12  74LCX14  (sections A,B,C,D,E,F)
U13  AT24C32  [TSSOP]
U14  W25X32  [TSSOP]
sheet 05. Decoder
C54  0.1uF
C55  0.1uF
C56  0.1uF
C57  0.1uF
C58  0.1uF
C76  0.1uF
R52  560
R53  560
R54  560
R55  560
R56  560
R57  560
R58  560
R59  560
U15  74LCX138
U16  74HC273
U17  74LCX32  (sections A,B,C,D)
U18  74LCX245MTC
U19  74LCX574
U26  74LCX574
sheet 06 LCD
C78  0.1uF
C82  1nF
C83  1nF
C84  10uF/16V
C85  0.1uF
C86  1nF
C87  1nF
CON3  XF10B11A0C1-4S
J12  HEADER 2
Q1  KRC102S
R67  10K
R68  100
R69  100
R70  10K
R71  10
R72  100
R73  4.7K
R74  120K
R76  10K
R77  100
U25  AK4183  [TMSOP-10P]
sheet 07. External Connector
C74  0.1uF
C75  10uF/16V
J8  HEADER 20X2
J9  HEADER 20X2
J13  HEADER 12
J14  HEADER 10
sheet 08. Power & Reset
C59  0.1uF
C60  10uF/16V
C61  220uF/16V
C62  0.1uF
C66  10uF/16V
C67  0.1uF
C69  0.1uF
C70  10uF/16V
C71  0.1uF
C72  10uF/16V
C73  0.1uF
C77  10uF/16V
C79  10uF/16V
C80  10uF/16V
J7  DC JACK
LED9  RED
LED12  RED
R61  560
R62  1K
R65  560
R66  10K
SW9  BL150-L-A-BK
SW11  SW TACT
U20  LM1117MPX-3.3  [SOT-223]
U22  R1161N331D
U23  R1172N331D

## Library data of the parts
C1 C66 = CAP_2
C2 = CAP_NP_23
C3 = CAP_NP_27
C4 C40 C50 C56 C62 C81 C87 = CAP_NP_3
C5 C49 C54 C69 C85 C88 = CAP_NP_4
C6 = CAP_NP_19
C7 = CAP_NP_21
C8 C45 C73 C76 C86 C89 = CAP_NP_5
C9 = CAP_NP_26
C10 = CAP_NP_15
C11 = CAP_NP_9
C12 C72 = CAP_5
C13 C37 C44 C53 C55 C67 C83 = CAP_NP_1
C14 = CAP_NP_8
C15 = CAP_NP_18
C16 = CAP_NP_25
C17 C39 C60 C75 = CAP
C18 C38 C80 = CAP_1
C19 C43 = CAP_NP_6
C20 C70 = CAP_6
C21 = CAP_NP_12
C22 C48 = CAP_NP_7
C23 = CAP_NP_13
C24 = CAP_NP_10
C25 = CAP_7
C26 = CAP_NP_14
C27 C79 = CAP_4
C28 C77 = CAP_3
C29 = CAP_NP_17
C30 = CAP_NP_24
C31 C36 C47 C51 C58 C71 C82 = CAP_NP_2
C32 = CAP_NP_20
C33 C41 C46 C52 C57 C59 C74 C78 = CAP_NP
C34 = CAP_NP_28
C35 = CAP_NP_22
C63 = CAP_NP_11
C200 = CAP_NP_16
J1 = USB_B
J2 = HEADER_5
J3 J6 J12 = HEADER_2
JP1 = HEADER_5X2_0
L1 L2 = INDUCTOR
OSC1 = 74LS138_0
P1 = CONNECTOR_DB9
R1-R6 R8 R11-R48 R52-R59 R61 R62 R65 R67-R74 R76-R78 R100 = R
R7 R66 = RESISTOR
R64 = RESISTOR_1
SW1 = SW_SL_SPDT_0
SW10 = SW_PUSHBUTTON-SPST-2_SM
U1 = MAX3232_SO_2
U2 = 74HC125_0
U3 = CANTUS_0
U27 = 78XX_TO92_1
Y1 = CRYSTAL_1
Y2 = CRYSTAL
C42 C61 C84 = C
CON1 CON2 = PHONEJACK_STEREO_SW_0
D1 = DIODE
D2 = DIODE_2
D3 = DIODE_1
Q4-Q7 = MOSFET_N
SW3-SW8 SW11 = SW_PUSHBUTTON
U4 = LM4861_0
U24 = FND4_0
VR1 = RESISTOR_VAR_0
J4 = HEADER_4X2
U5 = 74HC08_1
U6 U9 U18 = 74HC245_1
U7 U8 = 74HC574_2
J5 = 104G-TAA0-R_0
J15 = HEADER_25X2_1
J16 J17 = HEADER_3
R49 = R_6
R50 R51 = R_9
U10 = KM681000_5
U11 = NAND_5
U12 = 74LCX14_SO_9
U13 = NM24C16_0
U14 = NM24C16_1
U15 = 74HC138_0
U16 = 74HC273_0
U17 = 74HC32_0
U19 U26 = 74HC574_3
CON3 = HEADER_45
Q1 = NPN_BCE_0
U25 = AK4183
J8 J9 = HEADER_20X2
J13 = HEADER_12
J14 = HEADER_10
J7 = BNC_1
LED9 LED12 = LED_0
SW9 = SW_SL_SPDT_1
U20 = LM117_2
U22 = R1172x_0
U23 = R1172x_1

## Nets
AGND: C18.2 C19.2 C20.2 C21.2 C39.2 C40.2 C41.2 C42.2 CON1.1(E) J2.5 L2.1 R16.2 U3.15(CODEC_AVSS) U4.7(GND)
AV3P3D: C18.1 C19.1 J2.1 L1.2 U3.14(CODEC_AVDD33)
GND: C1.2 C2.2 C4.2 C5.2 C6.2 C8.2 C9.2 C10.2 C11.2 C12.2 C13.2 C14.2 C15.2 C16.2 C17.2 C22.2 C23.2 C24.2 C25.2 C26.2 C27.2 C28.2 C29.2 C30.2 C31.2 C32.2 C33.1 C34.2 C35.2 C43.2 C44.2 C45.2 C46.1 C47.2 C48.1 C49.2 C50.2 C51.2 C52.2 C53.2 C54.2 C55.1 C56.1 C57.2 C58.1 C59.2 C60.2 C61.2 C62.2 C63.1 C66.2 C67.2 C69.2 C70.2 C71.2 C72.2 C73.2 C74.2 C75.2 C76.1 C77.2 C78.2 C79.2 C80.2 C81.2 C82.2 C83.2 C84.2 C85.2 C86.2 C87.2 C88.2 C89.2 C200.2 CON3.2 CON3.7 CON3.37 J1.4(GND) J1.5(SHIELD1) J1.6(SHIELD2) J5.3(VSS) J5.6(VSS) J5.11(SW_COM) J5.14(VSS) J7.1(SHIELD) J7.3(SHIELD) J8.5 J8.6 J8.7 J8.8 J9.2 J13.3 J13.4 J13.10 J13.12 J14.1 J14.2 J14.9 J14.10 J15.1 J15.25 J15.26 J15.50 JP1.4 JP1.8 JP1.9 JP1.10 L2.2 LED9.2 LED12.2 OSC1.2(GND) P1.5 Q1.1(E) R3.1 R4.2 R46.2 R62.2 SW1.1 SW10.3 SW10.4 SW11.1 U1.15(GND) U2.2(I) U2.4(~{OE}) U2.7(GND) U2.10(~{OE}) U2.12(I) U3.11(VSS) U3.24(VSS) U3.37(VSS) U3.44(PMU_VSS) U3.49(ROSC_VSS) U3.55(PMU_LDO_VSS) U3.56(OSC_VSS) U3.61(PLL_AVSS) U3.63(LDO_VSS) U3.75(VSS) U3.80(VSS) U3.90(VSS) U5.7(GND) U6.10(GND) U7.1(~{OE}) U7.10(GND) U8.1(~{OE}) U8.10(GND) U9.7(A5) U9.8(A6) U9.9(A7) U9.10(GND) U9.19(~{OE}) U10.24(GND) U11.6(GND) U11.13(VSS) U11.36(VSS) U12.7(GND) U12.9(A) U12.11(A) U13.1(A0) U13.2(A1) U13.3(A2) U13.4(VSS) U13.7(NC) U14.4(VSS) U15.8(GND) U16.10(GND) U17.7(GND) U18.10(GND) U19.1(~{OE}) U19.10(GND) U20.1(GND) U22.2(GND) U23.2(GND) U25.6(GND) U26.1(~{OE}) U26.10(GND) U27.2(GND)
V1P8D: C8.1 C9.1 C10.1 C11.1 C12.1 C28.1 C29.1 C66.1 U3.25(CORE_VDD18) U3.59(OSC_VDD18) U3.62(PLL_AVDD18) U3.64(LDO_VDD18_OUT) U3.81(CORE_VDD18)
V1P8D_PMU: C26.1 C27.1 C31.1 C32.1 U3.45(PMU_VDD18) U3.50(ROSC_VDD18) U3.54(PMU_LDO_OUT18)
V3P3D: C1.1 C4.1 C5.1 C13.1 C15.1 C16.1 C17.1 C24.1 C25.1 C33.2 C34.1 C35.1 C41.1 C42.1 C43.1 C44.1 C46.2 C48.2 C49.1 C50.1 C51.1 C52.1 C53.1 C54.1 C55.2 C56.2 C57.1 C58.2 C59.1 C60.1 C67.1 C74.1 C75.1 C76.2 C78.1 C81.1 C84.1 C88.1 C89.1 J8.1 J8.2 J8.3 J8.4 J9.1 J13.1 J13.2 J15.12 J15.13 J15.14 J15.37 J15.38 J15.39 JP1.2 L1.1 OSC1.4(VCC) Q4.2(DRAIN) Q5.2(DRAIN) Q6.2(DRAIN) Q7.2(DRAIN) R1.1 R2.1 R17.1 R18.1 R19.1 R20.2 R21.2 R22.2 R23.2 R24.2 R25.2 R26.2 R27.2 R28.1 R29.1 R30.1 R31.1 R32.1 R33.1 R34.1 R35.1 R36.1 R37.1 R38.1 R39.2 R40.2 R41.2 R42.2 R43.2 R44.2 R45.2 R47.2 R48.2 R49.2 R50.1 R51.2 R61.2 R64.1 R66.1 R70.1 R73.1 R78.1 R100.1 U1.16(VCC) U2.13(~{OE}) U2.14(VCC) U3.1(nTEST) U3.10(IO_VDD33) U3.43(IO_VDD33) U3.53(PMU_LDO_VDD33) U3.60(OSC_VDD33) U3.65(LDO_VDD33_IN) U3.91(IO_VDD33) U4.6(VDD) U5.14(VCC) U6.20(VCC) U7.20(VCC) U8.20(VCC) U9.1(DIR) U9.20(VCC) U10.6(CS2) U10.8(VCC) U11.12(VCC) U11.37(VCC) U12.14(VCC) U13.8(VCC) U14.8(VCC) U15.16(VCC) U16.20(VCC) U17.14(VCC) U18.20(VCC) U19.20(VCC) U20.2(VOUT) U25.1(VCC) U26.20(VCC) U27.1(VCC)
V5P0D: C61.1 C62.1 C77.1 C79.1 C80.1 SW9.2 SW9.5 SW9.8 U20.3(VIN) U22.1(VDD) U22.4(ECO) U23.3(VDD)
A: R52.2 U24.11(A)
A0: CON3.35 J9.3 U7.19(Q1) U10.20(A0)
A1: J9.5 U7.18(Q2) U10.19(A1)
A2: J9.7 U7.17(Q3) U10.18(A2)
A3: J9.9 U7.16(Q4) U10.17(A3)
A4: J9.11 U7.15(Q5) U10.16(A4)
A5: J9.13 U7.14(Q6) U10.15(A5)
A6: J9.15 U7.13(Q7) U10.14(A6)
A7: J9.17 U7.12(Q8) U10.13(A7)
A8: J9.19 U8.12(Q8) U10.3(A8)
A9: J9.21 U8.13(Q7) U10.2(A9)
A10: J9.23 U8.14(Q6) U10.31(A10)
A11: J9.25 U8.15(Q5) U10.1(A11)
A12: J9.27 U8.16(Q4) U10.12(A12)
A13: J9.29 U8.17(Q3) U10.4(A13)
A14: J9.31 U8.18(Q2) U10.11(A14) U15.1(A)
A15: J9.33 U8.19(Q1) U10.7(A15) U15.2(B)
A16: J9.35 U3.40(P5.5/A16/CAP5/TMO5) U10.10(A16) U15.3(C)
A17: J9.37 U3.41(P5.6/A17/CAP6/TMO6) U15.6(G1)
A18: J9.39 J15.2 U3.42(P5.7/A18/CAP7/TMO7)
AD0: R20.1 U3.76(P0.0/A0/D0/A8/BOOTSEL0) U6.2(A0) U7.2(D1) U8.9(D8)
AD1: R21.1 U3.77(P0.1/A1/D1/A9/BOOTSEL1) U6.3(A1) U7.3(D2) U8.8(D7)
AD2: R22.1 U3.78(P0.2/A2/D2/A10/NFSIZ0) U6.4(A2) U7.4(D3) U8.7(D6)
AD3: R23.1 U3.79(P0.3/A3/D3/A11/NFSIZ1) U6.5(A3) U7.5(D4) U8.6(D5)
AD4: R24.1 U3.82(P0.4/A4/D4/A12/nISPSEL) U6.6(A4) U7.6(D5) U8.5(D4)
AD5: R25.1 U3.83(P0.5/A5/D5/A13/MEMSIZ) U6.7(A5) U7.7(D6) U8.4(D3)
AD6: R26.1 U3.84(P0.6/A6/D6/A14/nOSISEL) U6.8(A6) U7.8(D7) U8.3(D2)
AD7: R27.1 SW1.2 U3.85(P0.7/A7/D7/A15/nJTAGSEL) U6.9(A7) U7.9(D8) U8.2(D1)
AIN1: J2.2 U3.20(AIN1)
AIN2: J2.3 U3.21(AIN2)
AIN3: J2.4 U3.22(AIN3)
ALE0: R32.2 U2.5(I) U3.86(P2.0/SRAM_ALE0)
ALE1: R33.2 U2.9(I) U3.87(P2.1/SRAM_ALE1)
B: R53.2 U24.7(B)
BACK_nOFF: R67.2 R71.2 U16.5(Q2) U18.12(B6)
C: R54.2 U24.4(C)
CODE_VREF: C20.1 C21.1 U3.19(VREF)
CODEC_AOUT: C38.2 R16.1 U3.18(AOUT)
CODEC_VGA: R11.2 R12.1 U3.16(VGA)
CODEC_VOA: R12.2 U3.17(VOA)
COM1: Q4.3(SOURCE) U24.12(COM1)
COM1_CTL: Q4.1(GATE) U26.18(Q2)
COM2: Q5.3(SOURCE) U24.9(COM2)
COM2_CTL: Q5.1(GATE) U26.17(Q3)
COM3: Q6.3(SOURCE) U24.8(COM3)
COM3_CTL: Q6.1(GATE) U26.16(Q4)
COM4: Q7.3(SOURCE) U24.6(COM4)
COM4_CTL: Q7.1(GATE) U26.19(Q1)
D: R55.2 U24.2(D)
D0: CON3.31 J9.26 U6.18(B0) U10.21(D1) U11.29(I/O0) U16.3(D1) U18.9(A7) U19.9(D8) U26.2(D1)
D1: CON3.30 J9.28 U6.17(B1) U10.22(D2) U11.30(I/O1) U16.4(D2) U18.8(A6) U19.8(D7) U26.3(D2)
D2: CON3.29 J9.30 U6.16(B2) U10.23(D3) U11.31(I/O2) U16.7(D3) U18.7(A5) U19.7(D6) U26.4(D3)
D3: CON3.28 J9.32 U6.15(B3) U10.25(D4) U11.32(I/O3) U16.8(D4) U18.6(A4) U19.6(D5) U26.5(D4)
D3P3D: C69.1 C70.1 J5.4(VDD) U22.5(VOUT)
D4: CON3.27 J9.34 U6.14(B4) U10.26(D5) U11.41(I/O4) U16.13(D5) U18.5(A3) U19.5(D4) U26.6(D5)
D5: CON3.26 J9.36 U6.13(B5) U10.27(D6) U11.42(I/O5) U16.14(D6) U18.4(A2) U19.4(D3) U26.7(D6)
D6: CON3.25 J9.38 U6.12(B6) U10.28(D7) U11.43(I/O6) U16.17(D7) U18.3(A1) U19.3(D2) U26.8(D7)
D7: CON3.24 J9.40 U6.11(B7) U10.29(D8) U11.44(I/O7) U16.18(D8) U18.2(A0) U19.2(D1) U26.9(D8)
DP: R59.2 U24.3(DP)
E: R56.2 U24.1(E)
EIRQ0: J6.2 J8.24 U3.66(P3.0/nWAIT/EIRQ0) U14.1(\\~{C}S)
EIRQ1: J8.26 J12.2 U3.67(P3.1/nBE1/EIRQ1)
F: R57.2 U24.10(F)
G: R58.2 U24.5(G)
G2_nRESET: J15.27 U16.12(Q5) U18.15(B3)
GAIN_CTL: J14.6 U16.9(Q4) U18.14(B4)
IIS_LRCK: J8.32 J13.7 U3.36(P5.2/IIS_LRCK/CAP2/TMO2)
IIS_MCLK: J8.36 J13.9 U3.39(P5.4/IIS_MCLK/CAP4/TMO4)
IIS_SCLK: J8.34 J13.8 U3.38(P5.3/IIS_SCLK/CAP3/TMO3)
IIS_SDI: J8.30 J13.11 U3.27(P4.1/IIS_SDI/RX0)
IIS_SDO: J8.28 J13.6 U3.26(P4.0/IIS_SDO/TX0)
JTAG_TCK/P6.1: J8.18 J14.4 JP1.7 U3.97(P6.1/TCK)
JTAG_TDI/P6.3: J8.22 JP1.1 U3.99(P6.3/TDI)
JTAG_TDO: JP1.6 U3.100(TDO)
JTAG_TMS/P6.2: J8.20 J14.5 JP1.3 U3.98(P6.2/TMS)
JTAG_TRST/P6.0: J8.16 J14.3 JP1.5 U3.96(P6.0/TRST)
KEY_I0: J16.1 R18.2 SW3.1 SW4.1 SW5.1
KEY_I1: J8.15 R19.2 SW6.1 SW7.1 SW8.1 U3.5(P1.3/A11/D11/KEY_I1/RX5)
KEY_O0: D3.2 J17.1
KEY_O1: D2.2 J8.13 U3.4(P1.2/A10/D10/KEY_O1/TX5)
KEY_O2: D1.2 J8.17 U3.6(P1.4/A12/D12/KEY_O2/TX6)
L3P3D: C71.1 C72.1 C85.1 CON3.10 CON3.11 CON3.12 R65.2 R67.1 R68.2 R69.2 R72.2 R74.2 R76.1 R77.2 U23.1(VOUT)
LCD_nRESET: CON3.32 U16.15(Q6)
LCD_PWR: U16.2(Q1) U18.11(B7) U23.5(CE)
LED1+: CON3.38 R77.1
LED2+: CON3.39 R69.1
LED3+: CON3.40 R72.1
LED4+: CON3.41 R68.1
LED-: CON3.44 Q1.3(C)
NAND_ALE: J8.35 R34.2 U3.69(P3.3/NDFL_ALE) U11.17(ALE)
NAND_CLE: J8.33 R35.2 U3.70(P3.4/NDFL_CLE) U11.16(CLE)
NAND_nBUSY: J8.39 R37.2 U3.73(P3.7/NDFL_nBUSY/nNMI) U11.7(R/B)
NAND_nCS: J4.7 J8.31 R36.2 U3.71(P3.5/NDFL_nCS) U11.9(\\~{C}E)
NAND_nRE: J8.29 U3.72(P3.6/NDFL_nRE) U5.13(B) U11.8(\\~{R}E)
NAND_nWE: J8.37 R78.2 U3.68(P3.2/NDFL_nWE) U11.18(\\~{W}E)
nCS0: J4.1 U3.92(P2.4/SRAM_nCS0) U9.4(A2)
nCS0B: J9.8 U9.16(B2) U10.30(~{CS1})
nCS1: J4.3 J8.10 U3.93(P2.5/SRAM_nCS1) U9.3(A1)
nCS1_0: U15.15(~{Y0}) U17.1(A) U17.4(A)
nCS1_1: U15.14(~{Y1}) U17.9(A)
nCS1_2: U15.13(~{Y2}) U17.12(A)
nCS1_3: CON3.36 J9.14 U15.12(~{Y3})
nCS1_4: J9.16 U15.11(~{Y4})
nCS1_5: J9.18 U15.10(~{Y5})
nCS1_6: J9.20 U15.9(~{Y6})
nCS1_7: J9.22 U15.7(~{Y7})
nCS1B: J9.6 U9.17(B1) U15.4(~{G2A}) U15.5(~{G2B})
nCS2: J4.5 J8.14 U3.94(P2.6/SRAM_nCS2/ISP_nCS) U9.2(A0)
nCS2B: J9.4 U9.18(B0)
nRE: U3.88(P2.2/SRAM_nRE) U5.12(A) U9.5(A3)
nREB: CON3.33 J9.10 U9.15(B3) U10.32(~{OE}) U17.5(B)
nRESET: J8.25 J13.5 U12.6(Y) U16.1(~{CLR})
nRESET_CPU: C63.2 R64.2 SW10.1 SW10.2 U3.74(nRESET) U12.3(A) U27.3(OUT)
nWE: U3.89(P2.3/SRAM_nWE) U9.6(A4)
nWEB: CON3.34 J9.12 U9.14(B4) U10.5(~{WE}) U17.2(B) U17.10(B) U17.13(B)
P1.5: J8.19 R2.2 U2.1(~{OE}) U3.7(P1.5/A13/D13/KEY_IN2/RX6)
PC_RX0: P1.2 U1.14(T1OUT)
PC_TX0: P1.3 U1.13(R1IN)
PWK: C73.1 R66.2 SW11.2 U3.46(PWK)
RESET: J8.27 U12.4(Y) U12.5(A)
RX4: J8.11 J16.2 U3.3(P1.1/A9/D9/KEY_I0/RX4)
RX7: J8.23 U1.12(R1OUT) U3.9(P1.7/A15/D15/KEY_I3/RX7)
SD_CLK: J5.5(CLK) J15.4 R42.1 U3.30(P4.4/SDCD_CLK/SPI_SCK/TX2/ISP_CLK) U14.6(SCK)
SD_CMD: J5.2(CMD) R41.1 U3.31(P4.5/SDCD_CMD/RX2)
SD_D0: J5.7(DATA0) J15.3 R43.1 U3.35(P5.1/SDCD_D0/CAP1/TMO1)
SD_D1: J3.2 J5.8(DATA1) J15.28 R44.1 U3.34(P5.0/SDCD_D1/CAP0/TMO0/EXT_CLK)
SD_D2: J5.9(DATA2) J15.5 R45.1 U3.29(P4.3/SDCD_D2/SPI_MISO/RX1/ISP_OUT) U14.2(SO)
SD_D3: J5.1(DATA3) J15.29 R46.1 U3.28(P4.2/SDCD_D3/SPI_MOSI/TX1/ISP_IN) U14.5(SI)
SD_nDETECT: J5.10(DETECT) R40.1 U12.1(A)
SD_nWP: J5.12(\\~{WP}) R39.1 U18.18(B0)
SD_PWR: U16.6(Q3) U18.13(B5) U22.3(CE)
SHDOWN: R17.2 U3.23(P6.4/PORBY) U4.1(SHUTDOWN)
SPI_nSS: J8.12 J15.30 R49.1 U3.95(P2.7/SRAM_nCS3/SPI_nSS)
TWI_SCL: J8.38 J14.7 R47.1 U3.32(P4.6/TWI_SCL/TX3) U13.6(SCL) U25.10(SCL)
TWI_SDA: J8.40 J14.8 R48.1 U3.33(P4.7/TWI_SDA/RX3) U13.5(SDA) U25.9(SDA)
TX4: J8.9 J17.2 U3.2(P1.0/A8/D8/KEY_O0/TX4)
TX7: J8.21 U1.11(T1IN) U3.8(P1.6/A14/D14/KEY_O3/TX7)
USB_DM: R6.2 U3.13(USB_DM)
USB_DP: R5.2 U3.12(USB_DP)
USER_RX: J15.32 J17.3
USER_TX: J15.7 J16.3
XL: C86.1 CON3.6 U25.4(XN)
XR: C82.1 CON3.4 U25.2(XP)
YB: C87.1 CON3.3 U25.5(YN)
YT: C83.1 CON3.5 U25.3(YP)
N19775026: C200.1 R100.2 U3.48(PMU_nRESET)
N19840140: R50.2 U14.7(\\~{HOL}D)
N19863147: R51.1 U14.3(\\~{W}P)
N20284272: J1.3(D+) R1.2 R5.1 U2.3(O)
N20551223: C23.1 R8.1 U3.52(RTC_XOUT) Y2.2
N20551243: C30.1 R8.2 U3.51(RTC_XIN) Y2.1
N20558837: C14.1 R7.1 U3.58(XOUT) Y1.2
N20558852: C22.1 R7.2 U3.57(XIN) Y1.1
N20688352: C47.1 U2.8(O) U8.11(LE)
N20821328: LED9.1 R61.1
N20824885: LED12.1 R65.1
N20861346: U16.11(CLK) U17.3(Y)
N20968748: CON2.1(E) U4.8(VO2)
N20968771: C37.2 CON2.2(A) U4.5(VO1) VR1.1(A)
N20968773: R14.2 R15.1 U4.4(-IN)
N20968775: C39.1 C40.1 U4.2(BYPASS) U4.3(+IN)
N20968893: C38.1 R15.2
N20968895: R13.2 VR1.2(B) VR1.3(WIPER)
N20968939: C37.1 R13.1 R14.1
N20969114: C36.2 R11.1
N20969116: C36.1 CON1.2(A)
N20970079: J3.1 OSC1.3(CLK)
N21105225: U5.3(Y) U5.10(B)
N21179035: U5.11(Y) U6.1(DIR)
N21213760: J4.2 R28.2 U5.1(A)
N21213764: J4.4 R29.2 U5.2(B)
N21257041: D2.1 SW4.2 SW7.2
N21257043: D3.1 SW5.2 SW8.2
N21257165: D1.1 SW3.2 SW6.2
N21282145: C7.2 U1.5(C2-)
N21282153: C3.2 U1.3(C1-)
N21282157: C3.1 U1.1(C1+)
N21282171: C7.1 U1.4(C2+)
N21282173: C2.1 U1.2(V+)
N21282175: C6.1 U1.6(V-)
N21310274: J1.2(D-) R6.1
N21419801: U17.6(Y) U18.1(DIR) U18.19(~{OE})
N21517565: R38.2 U11.19(\\~{W}P)
N21638966: U5.6(Y) U5.9(A)
N21641251: U5.8(Y) U6.19(~{OE})
N21645012: J4.8 R31.2 U5.5(B)
N21701753: C45.1 U2.6(O) U7.11(LE)
N21711452: J4.6 R30.2 U5.4(A)
N21788804: J6.1 U12.2(Y)
N21913392: R58.1 U19.13(Q7)
N21913394: R57.1 U19.14(Q6)
N21913396: R56.1 U19.15(Q5)
N21913398: R55.1 U19.16(Q4)
N21913400: R54.1 U19.17(Q3)
N21913402: R53.1 U19.18(Q2)
N21913404: R52.1 U19.19(Q1)
N21913444: U17.8(Y) U19.11(CLK)
N21913514: U17.11(Y) U26.11(CLK)
N21913786: R59.1 U19.12(Q8)
N22028653: R62.1 SW9.7
N22275018: CON3.8 CON3.9 R76.2
N22275022: CON3.45 R74.1
N22275225: R70.2 U12.13(A) U25.7(PENIRQN)
N22275227: R73.2 U25.8(CAD0)
N22275275: Q1.2(B) R71.1
N22319872: J12.1 U12.12(Y)
N22509060: J7.2(CENTER) SW9.1 SW9.6
N23139918: R3.2 U1.10(T2IN)
N23139931: R4.1 U1.8(R2IN)

Not connected (* = marked no-connect by the designer): CON1 3(D)* 4(B)* 5(C)*; CON2 3(D)* 4(B)* 5(C)*; CON3 1* 13* 14* 15* 16 17 18 19 20 21 22 23 42* 43*; J1 1(VCC); J5 13(NC)*; J9 24; J15 6* 8* 9* 10* 11* 15* 16* 17* 18* 19* 20* 21* 22* 23* 24* 31* 33* 34* 35* 36* 40* 41* 42* 43* 44* 45* 46* 47* 48* 49*; OSC1 1(NC)*; P1 1* 4* 6* 7* 8* 9*; SW1 3*; SW9 3* 4*; U1 7(T2OUT) 9(R2OUT); U2 11(O); U3 47(PDN); U9 11(B7) 12(B6) 13(B5); U10 9(NC)*; U11 1(NC)* 2(NC)* 3(NC)* 4(NC)* 5(NC)* 10(NC)* 11(NC)* 14(NC)* 15(NC)* 20(NC)* 21(NC)* 22(NC)* 23(NC)* 24(NC)* 25(NC)* 26(NC)* 27(NC)* 28(NC)* 33(NC)* 34(NC)* 35(NC)* 38(NC)* 39(NC)* 40(NC)* 45(NC)* 46(NC)* 47(NC)* 48(NC)*; U12 8(Y) 10(Y); U16 16(Q7) 19(Q8); U18 16(B2) 17(B1); U23 4(NC)*; U26 12(Q8) 13(Q7) 14(Q6) 15(Q5)

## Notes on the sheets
sheet 1
- 眠啊
- CL=C14*C22/(C14+C22)+Co(6pF)
- Config MODE
- SW1
- NORMAL
- HIGH
- PMU RESET
- JTAG MODE
- LOW
- J3: Open-> SD Card
- J3: Short-> External Clock(Sound Sampling Clock)
- JTAG
sheet 2
- LINE INPUT
- LINE OUTPUT
sheet 3
- J4
- Mode
- 1-2 Short
- nCS0
- 3-4 Short
- nCS1
- 5-6 Short
- nCS2
- 7-8 Short
- NAND_nCS
- J4
- Mode
- 1-2 Open
- P2.4
- 3-4 Open
- P2.5
- 5-6 Open
- P2.6 or SPI_nSS
- 7-8 Open
- P3.5
sheet 4
- NAND
- SRAM
- Wi-Fi
- J16 2-3: RX4
  J16 1-2: KEY
- J17 2-3: TX4
  J17 1-2: KEY
- MODE
- J3
- J6
- SD Card
- Open
- Short
- MODE
- J16
- J17
- Ext Clock
- Short
- X
- SD CARD
- WI FI
- 2-3
- 2-3
- EIRQ
- X
- Open
- KEY MAT
- 1-2
- 1-2
- SPI Mem(U14)
- X
- Open
- UART
- 2-3
- 2-3
- Open
- TWI Serial EEPROM
- SPI Serial Flash
sheet 5
- nCS1: 0x6000 0000 ~ 0x6001 ffff->Device Control & User
- nCS1_0: 0x6002 0xxx -> Power Control
  nCS1_1: 0x6002 4xxx -> FND Cathode Control
  nCS1_2: 0x6002 8xxx -> FNA Anode Control
  nCS1_3: 0x6002 cxxx -> LCD Control
  nCS1_4: 0x6003 0xxx -> User
  nCS1_5: 0x6003 4xxx -> User
  nCS1_6: 0x6003 8xxx -> User
  nCS1_7: 0x6003 cxxx -> User
sheet 6
- 8Bit Mode
- MODE
- J12
- TOUCH
- Short
- EIRQ1
- OPEN
- I2812-7IMT2432A
- R68,R69,R72,R77  100ohm
- R68-->22ohm
  R69,R72,R77-->NC
- I2812-7IPT2432A
- CON3-->38,39,40,44pin short
sheet 7
- 43
- 38.1
- 6.03
- Audio CODEC I/F
- 6.03
- 6.03
sheet 8
- VOUT
- 1117
  SOT-223
- GND
- VOUT
- VIN
- 5VIN
- SD CARD POWER: 3.3V/300mA
- LCD POWER: 3.3V/1A
sheet 9
- ->  HISTORY  <-
- Date:
- 2009.9.8
- Version:
- 3.0
- 1. page 4: SPI Memory(U14) SPI_nSS甫 EIRQ0 栏肺 荐沥(SPI Memory客 SD Card甫 悼矫俊 荤侩 救窃)
     ->P6.2甫 荤侩窍咯 SPI Memory access
- 2. nCS3阑 SPI_nSS肺 荐沥
- 3. 扁粮狼 SPI_nSS甫 nCS2肺 荐沥
- 4. page 2: CN2甫 庆靛迄 棺 胶乔目肺档 免仿 窜 葛畴 鸥涝栏肺 免仿
- Date:
- 2010.2.5
- Version:
- 3.1
- 1. NC绰 楷搬窍瘤 富巴
- Date:
- 2010.5.19
- Version:
- 4.0
- 1. Main 1.8 Regulator 眠啊, 郴何 LDO荤侩秦档 凳.
- 2. Main 3.3V甫 1117肺 荐沥
- 3. Reset IC 眠啊
- 4. CANTUS 48锅巧阑 reset苞 楷搬
- 5. LCD Reset 矫弊澄 眠啊 棺 I2812-7IPT2432A 荤侩 规过 眠啊
- 6. SW2 力芭
- Date:
- 2010.8.24
- Version:
- 4.1
- 1. Main 1.8 Regulator 昏力
- Date:
- 2011.2.14
- Version:
- 4.1.1
- 1. Page2 net name 荐沥
     ->KEY O1>>狼 匙飘 匙烙阑 KEY_O2/TX6/P1_4甫 KEY O1/TX5/P1_2肺 荐沥
     ->KEY_O2>>狼 匙飘 匙烙阑 KEY_O2/TX6/P1_4肺 眠啊
  *焊靛俊辑绰 沥惑 利捞瘤父 雀肺档俊辑 net捞抚阑 肋给 汲沥.
- Date:
- 2017.3.14
- Version:
- 5.0
- 1. PMU Reset 荐沥(System Reset->RC Reset)
